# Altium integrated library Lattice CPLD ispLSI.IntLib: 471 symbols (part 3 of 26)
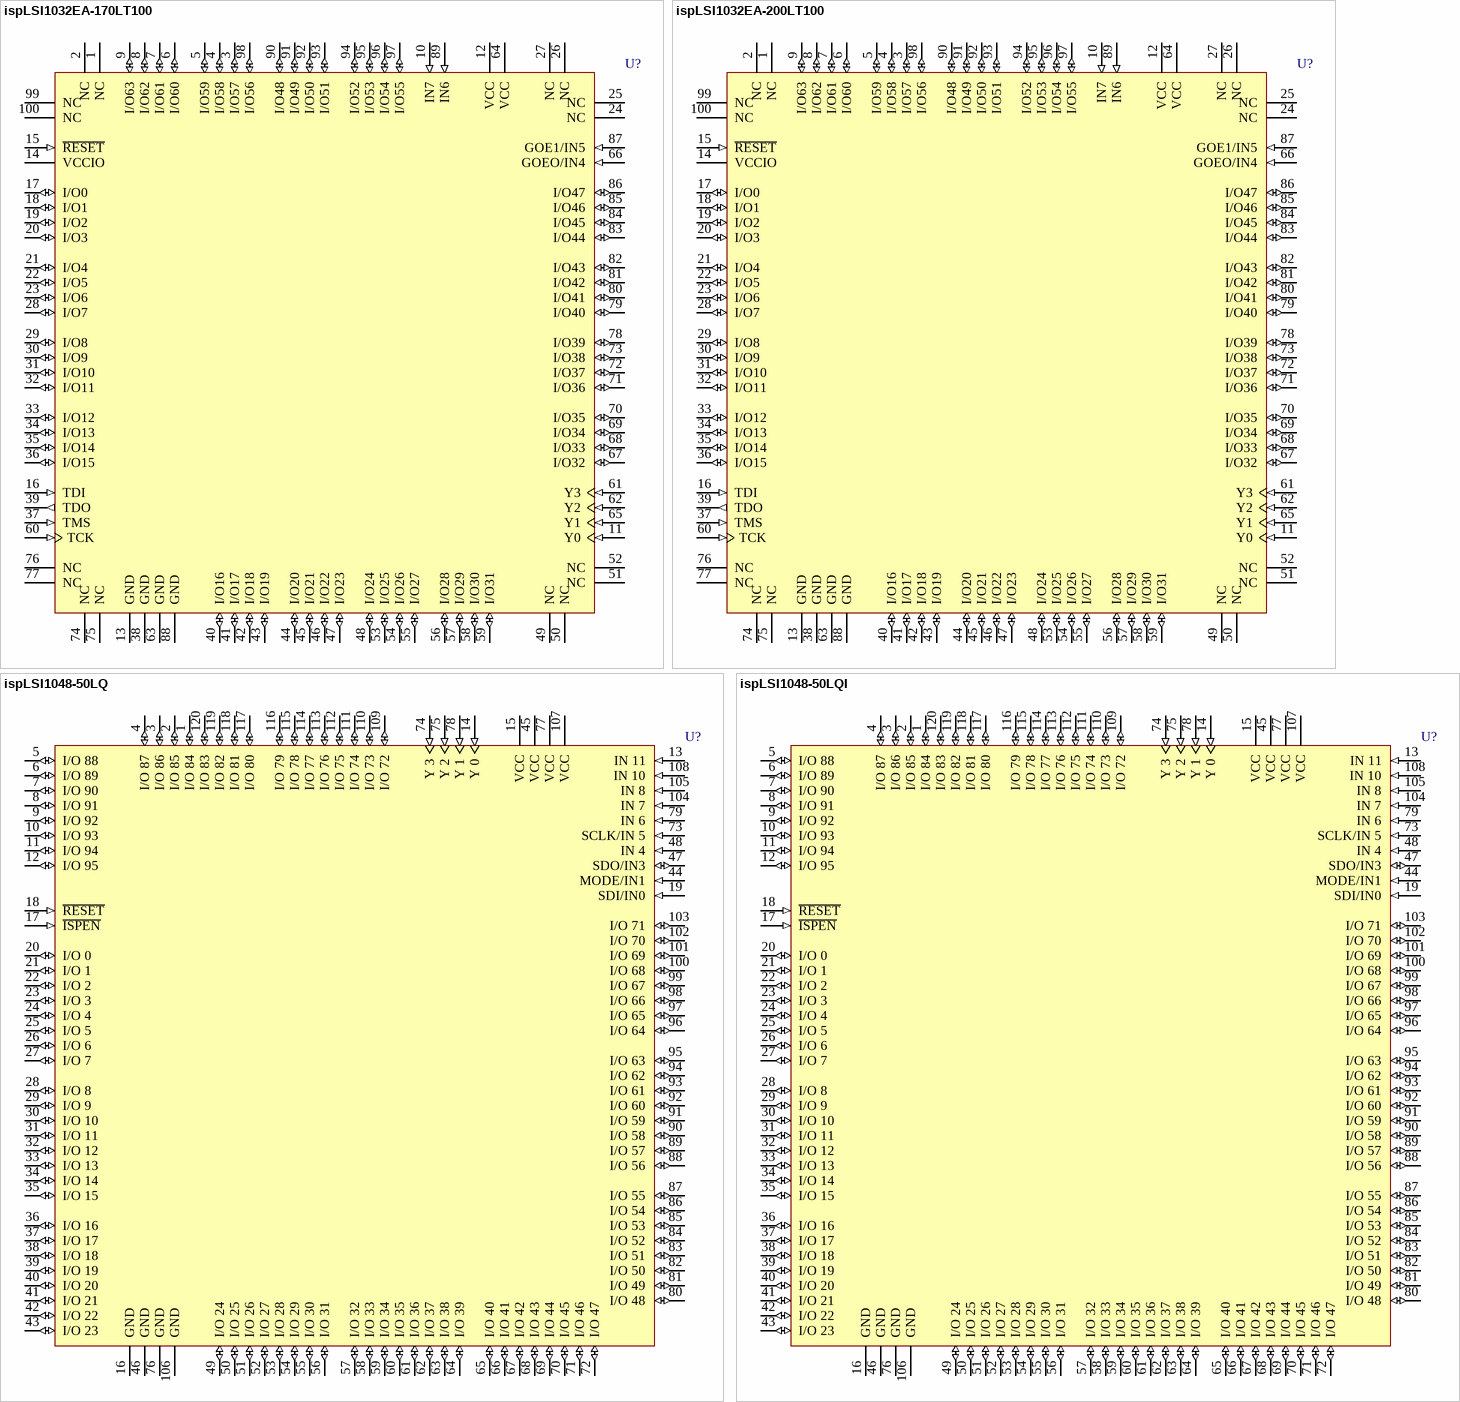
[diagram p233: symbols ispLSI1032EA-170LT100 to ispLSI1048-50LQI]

## ispLSI1032EA-200LT100
designator U?
In-System Programmable High-Density PLD; Note: Pins 66 and 87 have dual function capability which is software selectable.
footprint TQFP100_N (Thin QFP, 100-Leads, Body 14x14mm, Pitch 0.5mm, IPC Medium Density)
footprint TQFP100_L (Thin QFP, 100-Leads, Body 14x14mm, Pitch 0.5mm, IPC High Density)
footprint TQFP100_M (Thin QFP, 100-Leads, Body 14x14mm, Pitch 0.5mm, IPC Low Density)
3D model 1032EA-TQFP100 (100-Pin Thin Quad Flat Pack (TQFP100))
pins: 1 NC, 2 NC, 3 I/O57 (io), 4 I/O58 (io), 5 I/O59 (io), 6 I/O60 (io), 7 I/O61 (io), 8 I/O62 (io), 9 I/O63 (io), 10 IN7 (in), 11 Y0 (in), 12 VCC (power), 13 GND (power), 14 VCCIO (power), 15 ~{RESET} (in), 16 TDI (in), 17 I/O0 (io), 18 I/O1 (io), 19 I/O2 (io), 20 I/O3 (io), 21 I/O4 (io), 22 I/O5 (io), 23 I/O6 (io), 24 NC, 25 NC, 26 NC, 27 NC, 28 I/O7 (io), 29 I/O8 (io), 30 I/O9 (io), 31 I/O10 (io), 32 I/O11 (io), 33 I/O12 (io), 34 I/O13 (io), 35 I/O14 (io), 36 I/O15 (io), 37 TMS (in), 38 GND (power), 39 TDO (out), 40 I/O16 (io), 41 I/O17 (io), 42 I/O18 (io), 43 I/O19 (io), 44 I/O20 (io), 45 I/O21 (io), 46 I/O22 (io), 47 I/O23 (io), 48 I/O24 (io), 49 NC, 50 NC, 51 NC, 52 NC, 53 I/O25 (io), 54 I/O26 (io), 55 I/O27 (io), 56 I/O28 (io), 57 I/O29 (io), 58 I/O30 (io), 59 I/O31 (io), 60 TCK (in), 61 Y3 (in), 62 Y2 (in), 63 GND (power), 64 VCC (power), 65 Y1 (in), 66 GOEO/IN4 (in), 67 I/O32 (io), 68 I/O33 (io), 69 I/O34 (io), 70 I/O35 (io), 71 I/O36 (io), 72 I/O37 (io), 73 I/O38 (io), 74 NC, 75 NC, 76 NC, 77 NC, 78 I/O39 (io), 79 I/O40 (io), 80 I/O41 (io), 81 I/O42 (io), 82 I/O43 (io), 83 I/O44 (io), 84 I/O45 (io), 85 I/O46 (io), 86 I/O47 (io), 87 GOE1/IN5 (in), 88 GND (power), 89 IN6 (in), 90 I/O48 (io), 91 I/O49 (io), 92 I/O50 (io), 93 I/O51 (io), 94 I/O52 (io), 95 I/O53 (io), 96 I/O54 (io), 97 I/O55 (io), 98 I/O56 (io), 99 NC, 100 NC

## ispLSI1048-50LQ
designator U?
High-Density Programmable Logic
footprint PQFP120_N (QFP, 120-Leads, Body 28x28mm, Pitch 0.8mm, IPC Medium Density)
footprint PQFP120_L (QFP, 120-Leads, Body 28x28mm, Pitch 0.8mm, IPC High Density)
footprint PQFP120_M (QFP, 120-Leads, Body 28x28mm, Pitch 0.8mm, IPC Low Density)
3D model 1048-PQFP120 (120-Pin Quad Flat Pack 0.8 mm Pitch)
pins: 1 I/O 84 (io), 2 I/O 85 (io), 3 I/O 86 (io), 4 I/O 87 (io), 5 I/O 88 (io), 6 I/O 89 (io), 7 I/O 90 (io), 8 I/O 91 (io), 9 I/O 92 (io), 10 I/O 93 (io), 11 I/O 94 (io), 12 I/O 95 (io), 13 IN 11 (in), 14 Y 0 (in), 15 VCC (power), 16 GND (power), 17 ~{ISPEN} (in), 18 ~{RESET} (in), 19 SDI/IN0 (in), 20 I/O 0 (io), 21 I/O 1 (io), 22 I/O 2 (io), 23 I/O 3 (io), 24 I/O 4 (io), 25 I/O 5 (io), 26 I/O 6 (io), 27 I/O 7 (io), 28 I/O 8 (io), 29 I/O 9 (io), 30 I/O 10 (io), 31 I/O 11 (io), 32 I/O 12 (io), 33 I/O 13 (io), 34 I/O 14 (io), 35 I/O 15 (io), 36 I/O 16 (io), 37 I/O 17 (io), 38 I/O 18 (io), 39 I/O 19 (io), 40 I/O 20 (io), 41 I/O 21 (io), 42 I/O 22 (io), 43 I/O 23 (io), 44 MODE/IN1 (in), 45 VCC (power), 46 GND (power), 47 SDO/IN3 (io), 48 IN 4 (in), 49 I/O 24 (io), 50 I/O 25 (io), 51 I/O 26 (io), 52 I/O 27 (io), 53 I/O 28 (io), 54 I/O 29 (io), 55 I/O 30 (io), 56 I/O 31 (io), 57 I/O 32 (io), 58 I/O 33 (io), 59 I/O 34 (io), 60 I/O 35 (io), 61 I/O 36 (io), 62 I/O 37 (io), 63 I/O 38 (io), 64 I/O 39 (io), 65 I/O 40 (io), 66 I/O 41 (io), 67 I/O 42 (io), 68 I/O 43 (io), 69 I/O 44 (io), 70 I/O 45 (io), 71 I/O 46 (io), 72 I/O 47 (io), 73 SCLK/IN 5 (in), 74 Y 3 (in), 75 Y 2 (in), 76 GND (power), 77 VCC (power), 78 Y 1 (in), 79 IN 6 (in), 80 I/O 48 (io), 81 I/O 49 (io), 82 I/O 50 (io), 83 I/O 51 (io), 84 I/O 52 (io), 85 I/O 53 (io), 86 I/O 54 (io), 87 I/O 55 (io), 88 I/O 56 (io), 89 I/O 57 (io), 90 I/O 58 (io), 91 I/O 59 (io), 92 I/O 60 (io), 93 I/O 61 (io), 94 I/O 62 (io), 95 I/O 63 (io), 96 I/O 64 (io), 97 I/O 65 (io), 98 I/O 66 (io), 99 I/O 67 (io), 100 I/O 68 (io), 101 I/O 69 (io), 102 I/O 70 (io), 103 I/O 71 (io), 104 IN 7 (in), 105 IN 8 (in), 106 GND (power), 107 VCC (power), 108 IN 10 (in), 109 I/O 72 (io), 110 I/O 73 (io), 111 I/O 74 (io), 112 I/O 75 (io), 113 I/O 76 (io), 114 I/O 77 (io), 115 I/O 78 (io), 116 I/O 79 (io), 117 I/O 80 (io), 118 I/O 81 (io), 119 I/O 82 (io), 120 I/O 83 (io)

## ispLSI1048-50LQI
designator U?
High-Density Programmable Logic
footprint PQFP120_N (QFP, 120-Leads, Body 28x28mm, Pitch 0.8mm, IPC Medium Density)
footprint PQFP120_L (QFP, 120-Leads, Body 28x28mm, Pitch 0.8mm, IPC High Density)
footprint PQFP120_M (QFP, 120-Leads, Body 28x28mm, Pitch 0.8mm, IPC Low Density)
3D model 1048-PQFP120 (120-Pin Quad Flat Pack 0.8 mm Pitch)
pins: 1 I/O 84 (io), 2 I/O 85 (io), 3 I/O 86 (io), 4 I/O 87 (io), 5 I/O 88 (io), 6 I/O 89 (io), 7 I/O 90 (io), 8 I/O 91 (io), 9 I/O 92 (io), 10 I/O 93 (io), 11 I/O 94 (io), 12 I/O 95 (io), 13 IN 11 (in), 14 Y 0 (in), 15 VCC (power), 16 GND (power), 17 ~{ISPEN} (in), 18 ~{RESET} (in), 19 SDI/IN0 (in), 20 I/O 0 (io), 21 I/O 1 (io), 22 I/O 2 (io), 23 I/O 3 (io), 24 I/O 4 (io), 25 I/O 5 (io), 26 I/O 6 (io), 27 I/O 7 (io), 28 I/O 8 (io), 29 I/O 9 (io), 30 I/O 10 (io), 31 I/O 11 (io), 32 I/O 12 (io), 33 I/O 13 (io), 34 I/O 14 (io), 35 I/O 15 (io), 36 I/O 16 (io), 37 I/O 17 (io), 38 I/O 18 (io), 39 I/O 19 (io), 40 I/O 20 (io), 41 I/O 21 (io), 42 I/O 22 (io), 43 I/O 23 (io), 44 MODE/IN1 (in), 45 VCC (power), 46 GND (power), 47 SDO/IN3 (io), 48 IN 4 (in), 49 I/O 24 (io), 50 I/O 25 (io), 51 I/O 26 (io), 52 I/O 27 (io), 53 I/O 28 (io), 54 I/O 29 (io), 55 I/O 30 (io), 56 I/O 31 (io), 57 I/O 32 (io), 58 I/O 33 (io), 59 I/O 34 (io), 60 I/O 35 (io), 61 I/O 36 (io), 62 I/O 37 (io), 63 I/O 38 (io), 64 I/O 39 (io), 65 I/O 40 (io), 66 I/O 41 (io), 67 I/O 42 (io), 68 I/O 43 (io), 69 I/O 44 (io), 70 I/O 45 (io), 71 I/O 46 (io), 72 I/O 47 (io), 73 SCLK/IN 5 (in), 74 Y 3 (in), 75 Y 2 (in), 76 GND (power), 77 VCC (power), 78 Y 1 (in), 79 IN 6 (in), 80 I/O 48 (io), 81 I/O 49 (io), 82 I/O 50 (io), 83 I/O 51 (io), 84 I/O 52 (io), 85 I/O 53 (io), 86 I/O 54 (io), 87 I/O 55 (io), 88 I/O 56 (io), 89 I/O 57 (io), 90 I/O 58 (io), 91 I/O 59 (io), 92 I/O 60 (io), 93 I/O 61 (io), 94 I/O 62 (io), 95 I/O 63 (io), 96 I/O 64 (io), 97 I/O 65 (io), 98 I/O 66 (io), 99 I/O 67 (io), 100 I/O 68 (io), 101 I/O 69 (io), 102 I/O 70 (io), 103 I/O 71 (io), 104 IN 7 (in), 105 IN 8 (in), 106 GND (power), 107 VCC (power), 108 IN 10 (in), 109 I/O 72 (io), 110 I/O 73 (io), 111 I/O 74 (io), 112 I/O 75 (io), 113 I/O 76 (io), 114 I/O 77 (io), 115 I/O 78 (io), 116 I/O 79 (io), 117 I/O 80 (io), 118 I/O 81 (io), 119 I/O 82 (io), 120 I/O 83 (io)

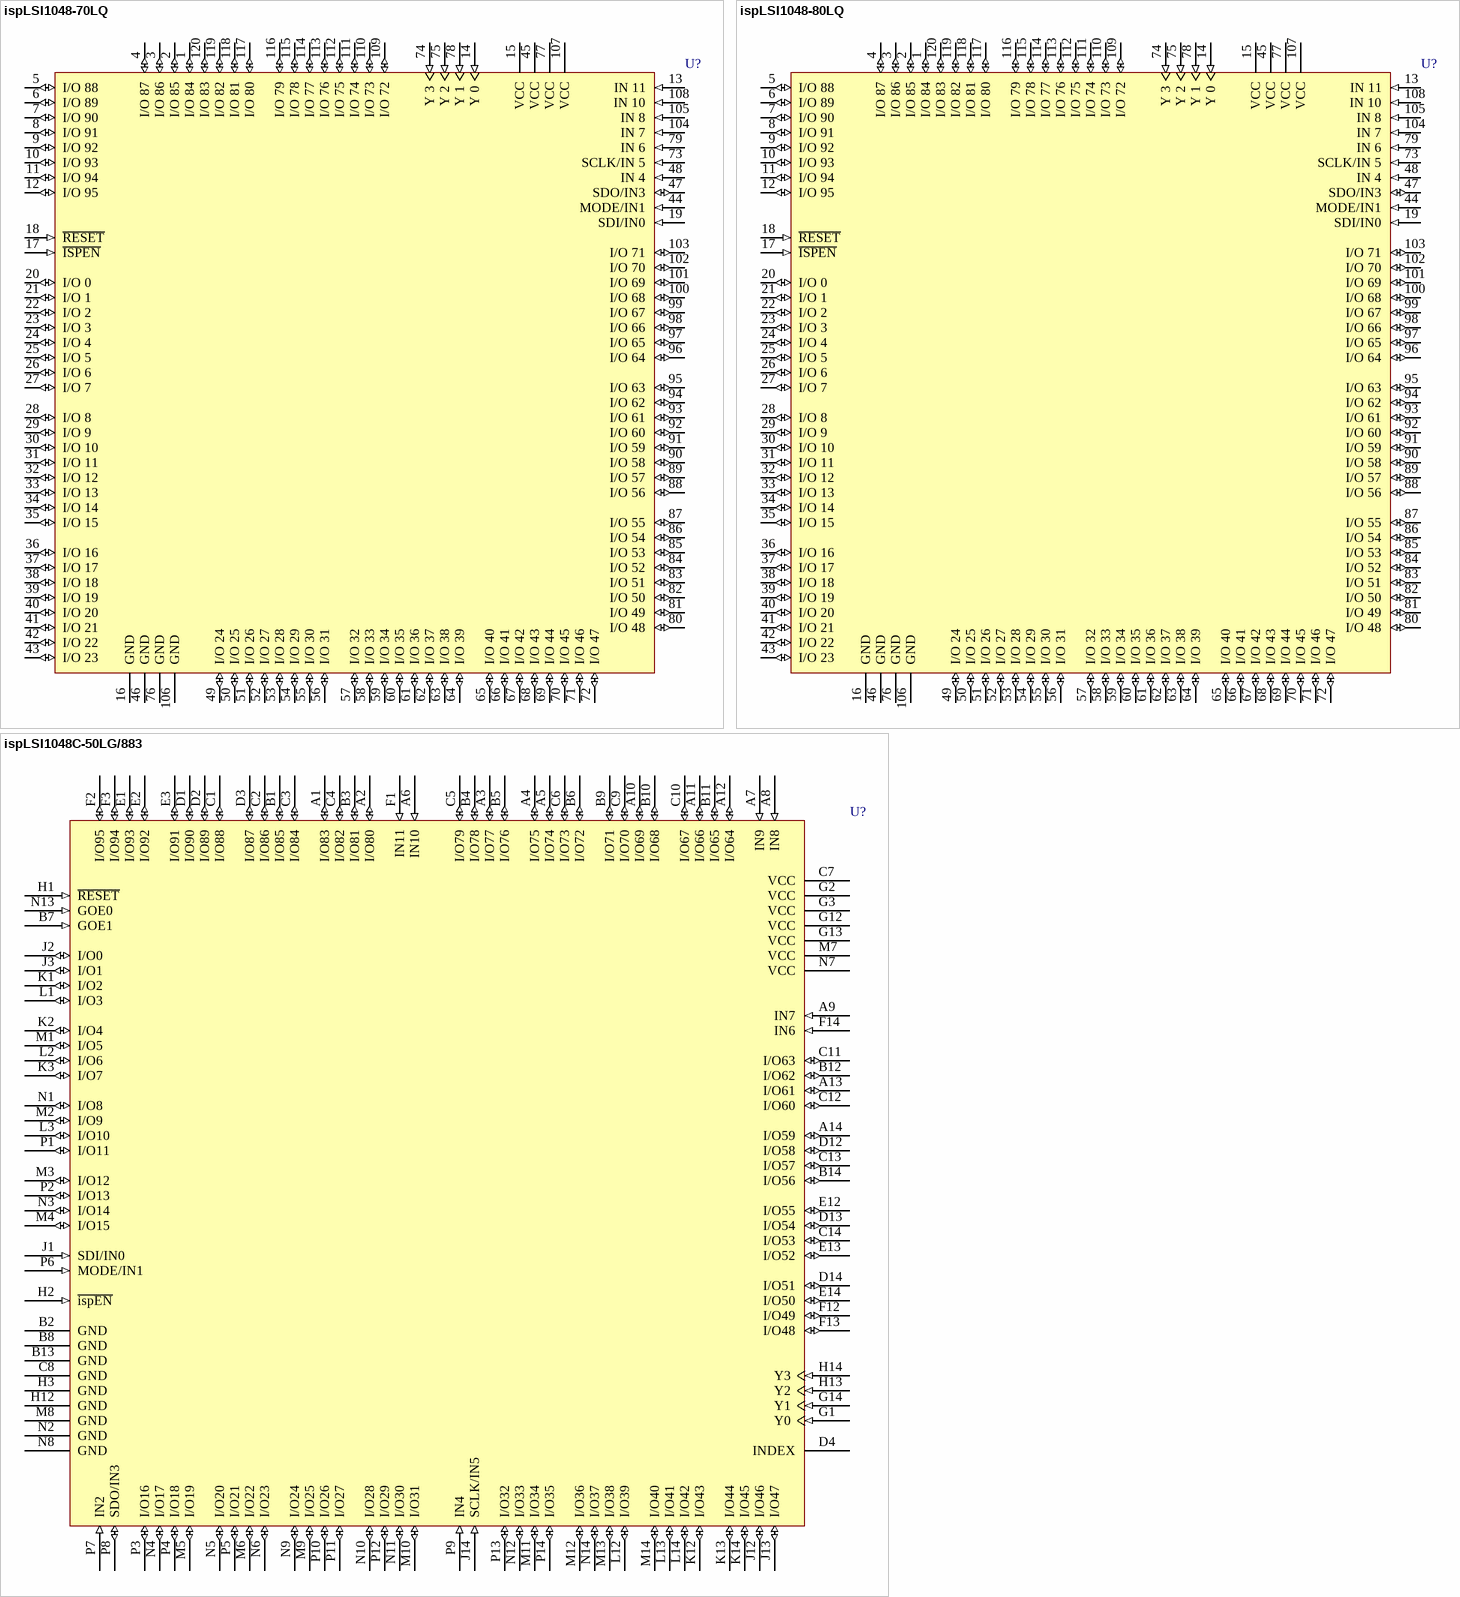
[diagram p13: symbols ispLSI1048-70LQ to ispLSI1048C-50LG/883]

## ispLSI1048-70LQ
designator U?
High-Density Programmable Logic
footprint PQFP120_N (QFP, 120-Leads, Body 28x28mm, Pitch 0.8mm, IPC Medium Density)
footprint PQFP120_L (QFP, 120-Leads, Body 28x28mm, Pitch 0.8mm, IPC High Density)
footprint PQFP120_M (QFP, 120-Leads, Body 28x28mm, Pitch 0.8mm, IPC Low Density)
3D model 1048-PQFP120 (120-Pin Quad Flat Pack 0.8 mm Pitch)
pins: 1 I/O 84 (io), 2 I/O 85 (io), 3 I/O 86 (io), 4 I/O 87 (io), 5 I/O 88 (io), 6 I/O 89 (io), 7 I/O 90 (io), 8 I/O 91 (io), 9 I/O 92 (io), 10 I/O 93 (io), 11 I/O 94 (io), 12 I/O 95 (io), 13 IN 11 (in), 14 Y 0 (in), 15 VCC (power), 16 GND (power), 17 ~{ISPEN} (in), 18 ~{RESET} (in), 19 SDI/IN0 (in), 20 I/O 0 (io), 21 I/O 1 (io), 22 I/O 2 (io), 23 I/O 3 (io), 24 I/O 4 (io), 25 I/O 5 (io), 26 I/O 6 (io), 27 I/O 7 (io), 28 I/O 8 (io), 29 I/O 9 (io), 30 I/O 10 (io), 31 I/O 11 (io), 32 I/O 12 (io), 33 I/O 13 (io), 34 I/O 14 (io), 35 I/O 15 (io), 36 I/O 16 (io), 37 I/O 17 (io), 38 I/O 18 (io), 39 I/O 19 (io), 40 I/O 20 (io), 41 I/O 21 (io), 42 I/O 22 (io), 43 I/O 23 (io), 44 MODE/IN1 (in), 45 VCC (power), 46 GND (power), 47 SDO/IN3 (io), 48 IN 4 (in), 49 I/O 24 (io), 50 I/O 25 (io), 51 I/O 26 (io), 52 I/O 27 (io), 53 I/O 28 (io), 54 I/O 29 (io), 55 I/O 30 (io), 56 I/O 31 (io), 57 I/O 32 (io), 58 I/O 33 (io), 59 I/O 34 (io), 60 I/O 35 (io), 61 I/O 36 (io), 62 I/O 37 (io), 63 I/O 38 (io), 64 I/O 39 (io), 65 I/O 40 (io), 66 I/O 41 (io), 67 I/O 42 (io), 68 I/O 43 (io), 69 I/O 44 (io), 70 I/O 45 (io), 71 I/O 46 (io), 72 I/O 47 (io), 73 SCLK/IN 5 (in), 74 Y 3 (in), 75 Y 2 (in), 76 GND (power), 77 VCC (power), 78 Y 1 (in), 79 IN 6 (in), 80 I/O 48 (io), 81 I/O 49 (io), 82 I/O 50 (io), 83 I/O 51 (io), 84 I/O 52 (io), 85 I/O 53 (io), 86 I/O 54 (io), 87 I/O 55 (io), 88 I/O 56 (io), 89 I/O 57 (io), 90 I/O 58 (io), 91 I/O 59 (io), 92 I/O 60 (io), 93 I/O 61 (io), 94 I/O 62 (io), 95 I/O 63 (io), 96 I/O 64 (io), 97 I/O 65 (io), 98 I/O 66 (io), 99 I/O 67 (io), 100 I/O 68 (io), 101 I/O 69 (io), 102 I/O 70 (io), 103 I/O 71 (io), 104 IN 7 (in), 105 IN 8 (in), 106 GND (power), 107 VCC (power), 108 IN 10 (in), 109 I/O 72 (io), 110 I/O 73 (io), 111 I/O 74 (io), 112 I/O 75 (io), 113 I/O 76 (io), 114 I/O 77 (io), 115 I/O 78 (io), 116 I/O 79 (io), 117 I/O 80 (io), 118 I/O 81 (io), 119 I/O 82 (io), 120 I/O 83 (io)

## ispLSI1048-80LQ
designator U?
High-Density Programmable Logic
footprint PQFP120_N (QFP, 120-Leads, Body 28x28mm, Pitch 0.8mm, IPC Medium Density)
footprint PQFP120_L (QFP, 120-Leads, Body 28x28mm, Pitch 0.8mm, IPC High Density)
footprint PQFP120_M (QFP, 120-Leads, Body 28x28mm, Pitch 0.8mm, IPC Low Density)
3D model 1048-PQFP120 (120-Pin Quad Flat Pack 0.8 mm Pitch)
pins: 1 I/O 84 (io), 2 I/O 85 (io), 3 I/O 86 (io), 4 I/O 87 (io), 5 I/O 88 (io), 6 I/O 89 (io), 7 I/O 90 (io), 8 I/O 91 (io), 9 I/O 92 (io), 10 I/O 93 (io), 11 I/O 94 (io), 12 I/O 95 (io), 13 IN 11 (in), 14 Y 0 (in), 15 VCC (power), 16 GND (power), 17 ~{ISPEN} (in), 18 ~{RESET} (in), 19 SDI/IN0 (in), 20 I/O 0 (io), 21 I/O 1 (io), 22 I/O 2 (io), 23 I/O 3 (io), 24 I/O 4 (io), 25 I/O 5 (io), 26 I/O 6 (io), 27 I/O 7 (io), 28 I/O 8 (io), 29 I/O 9 (io), 30 I/O 10 (io), 31 I/O 11 (io), 32 I/O 12 (io), 33 I/O 13 (io), 34 I/O 14 (io), 35 I/O 15 (io), 36 I/O 16 (io), 37 I/O 17 (io), 38 I/O 18 (io), 39 I/O 19 (io), 40 I/O 20 (io), 41 I/O 21 (io), 42 I/O 22 (io), 43 I/O 23 (io), 44 MODE/IN1 (in), 45 VCC (power), 46 GND (power), 47 SDO/IN3 (io), 48 IN 4 (in), 49 I/O 24 (io), 50 I/O 25 (io), 51 I/O 26 (io), 52 I/O 27 (io), 53 I/O 28 (io), 54 I/O 29 (io), 55 I/O 30 (io), 56 I/O 31 (io), 57 I/O 32 (io), 58 I/O 33 (io), 59 I/O 34 (io), 60 I/O 35 (io), 61 I/O 36 (io), 62 I/O 37 (io), 63 I/O 38 (io), 64 I/O 39 (io), 65 I/O 40 (io), 66 I/O 41 (io), 67 I/O 42 (io), 68 I/O 43 (io), 69 I/O 44 (io), 70 I/O 45 (io), 71 I/O 46 (io), 72 I/O 47 (io), 73 SCLK/IN 5 (in), 74 Y 3 (in), 75 Y 2 (in), 76 GND (power), 77 VCC (power), 78 Y 1 (in), 79 IN 6 (in), 80 I/O 48 (io), 81 I/O 49 (io), 82 I/O 50 (io), 83 I/O 51 (io), 84 I/O 52 (io), 85 I/O 53 (io), 86 I/O 54 (io), 87 I/O 55 (io), 88 I/O 56 (io), 89 I/O 57 (io), 90 I/O 58 (io), 91 I/O 59 (io), 92 I/O 60 (io), 93 I/O 61 (io), 94 I/O 62 (io), 95 I/O 63 (io), 96 I/O 64 (io), 97 I/O 65 (io), 98 I/O 66 (io), 99 I/O 67 (io), 100 I/O 68 (io), 101 I/O 69 (io), 102 I/O 70 (io), 103 I/O 71 (io), 104 IN 7 (in), 105 IN 8 (in), 106 GND (power), 107 VCC (power), 108 IN 10 (in), 109 I/O 72 (io), 110 I/O 73 (io), 111 I/O 74 (io), 112 I/O 75 (io), 113 I/O 76 (io), 114 I/O 77 (io), 115 I/O 78 (io), 116 I/O 79 (io), 117 I/O 80 (io), 118 I/O 81 (io), 119 I/O 82 (io), 120 I/O 83 (io)

## ispLSI1048C-50LG/883
designator U?
In-System Programmable High-Density PLD; Note: Pins J1, P6, P8 and J14 have dual function capability.
footprint CPGA133 (PGA, 133-Leads, Body 37x37mm, Pitch 2.54mm)
3D model 1048C-CPGA133 (133-Pin Pin Grid Array 2.54 mm Pitch)
pins: A1 I/O83 (io), A2 I/O80 (io), A3 I/O77 (io), A4 I/O75 (io), A5 I/O74 (io), A6 IN10 (in), A7 IN9 (in), A8 IN8 (in), A9 IN7 (in), A10 I/O69 (io), A11 I/O66 (io), A12 I/O64 (io), A13 I/O61 (io), A14 I/O59 (io), B1 I/O85 (io), B2 GND (power), B3 I/O81 (io), B4 I/O78 (io), B5 I/O76 (io), B6 I/O72 (io), B7 GOE1 (in), B8 GND (power), B9 I/O71 (io), B10 I/O68 (io), B11 I/O65 (io), B12 I/O62 (io), B13 GND (power), B14 I/O56 (io), C1 I/O88 (io), C2 I/O86 (io), C3 I/O84 (io), C4 I/O82 (io), C5 I/O79 (io), C6 I/O73 (io), C7 VCC (power), C8 GND (power), C9 I/O70 (io), C10 I/O67 (io), C11 I/O63 (io), C12 I/O60 (io), C13 I/O57 (io), C14 I/O53 (io), D1 I/O90 (io), D2 I/O89 (io), D3 I/O87 (io), D4 INDEX, D12 I/O58 (io), D13 I/O54 (io), D14 I/O51 (io), E1 I/O93 (io), E2 I/O92 (io), E3 I/O91 (io), E12 I/O55 (io), E13 I/O52 (io), E14 I/O50 (io), F1 IN11 (in), F2 I/O95 (io), F3 I/O94 (io), F12 I/O49 (io), F13 I/O48 (io), F14 IN6 (in), G1 Y0 (in), G2 VCC (power), G3 VCC (power), G12 VCC (power), G13 VCC (power), G14 Y1 (in), H1 ~{RESET} (in), H2 ~{ispEN} (in), H3 GND (power), H12 GND (power), H13 Y2 (in), H14 Y3 (in), J1 SDI/IN0 (in), J2 I/O0 (io), J3 I/O1 (io), J12 I/O46 (io), J13 I/O47 (io), J14 SCLK/IN5 (in), K1 I/O2 (io), K2 I/O4 (io), K3 I/O7 (io), K12 I/O43 (io), K13 I/O44 (io), K14 I/O45 (io), L1 I/O3 (io), L2 I/O6 (io), L3 I/O10 (io), L12 I/O39 (io), L13 I/O41 (io), L14 I/O42 (io), M1 I/O5 (io), M2 I/O9 (io), M3 I/O12 (io), M4 I/O15 (io), M5 I/O19 (io), M6 I/O22 (io), M7 VCC (power), M8 GND (power), M9 I/O25 (io), M10 I/O31 (io), M11 I/O34 (io), M12 I/O36 (io), M13 I/O38 (io), M14 I/O40 (io), N1 I/O8 (io), N2 GND (power), N3 I/O14 (io), N4 I/O17 (io), N5 I/O20 (io), N6 I/O23 (io), N7 VCC (power), N8 GND (power), N9 I/O24 (io), N10 I/O28 (io), N11 I/O30 (io), N12 I/O33 (io), N13 GOE0 (in), N14 I/O37 (io), P1 I/O11 (io), P2 I/O13 (io), P3 I/O16 (io), P4 I/O18 (io), P5 I/O21 (io), P6 MODE/IN1 (in), P7 IN2 (in), P8 SDO/IN3 (io), P9 IN4 (in), P10 I/O26 (io), P11 I/O27 (io), P12 I/O29 (io), P13 I/O32 (io), P14 I/O35 (io)

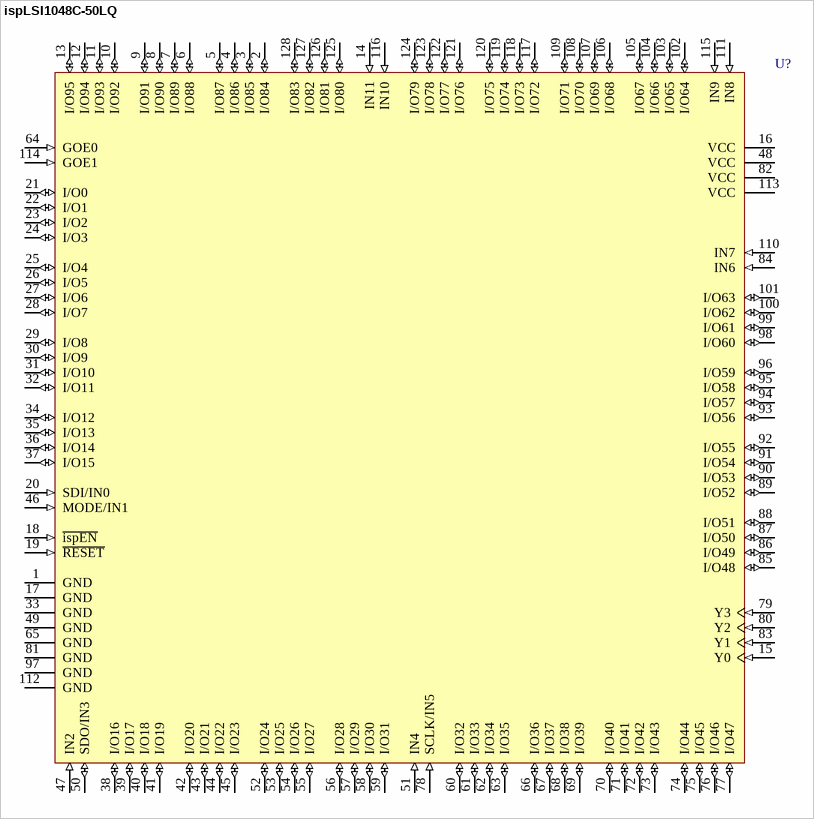
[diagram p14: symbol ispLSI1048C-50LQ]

## ispLSI1048C-50LQ
designator U?
In-System Programmable High-Density PLD; Note: Pins 20, 46, 50 and 78 have dual function capability.
footprint PQFP128_N (QFP, 128-Leads, Body 28x28mm, Pitch 0.8mm, IPC Medium Density)
footprint PQFP128_L (QFP, 128-Leads, Body 28x28mm, Pitch 0.8mm, IPC High Density)
footprint PQFP128_M (QFP, 128-Leads, Body 28x28mm, Pitch 0.8mm, IPC Low Density)
3D model 1048C-PQFP128 (128-Pin Quad Flat Pack 0.8 mm Pitch)
pins: 1 GND (power), 2 I/O84 (io), 3 I/O85 (io), 4 I/O86 (io), 5 I/O87 (io), 6 I/O88 (io), 7 I/O89 (io), 8 I/O90 (io), 9 I/O91 (io), 10 I/O92 (io), 11 I/O93 (io), 12 I/O94 (io), 13 I/O95 (io), 14 IN11 (in), 15 Y0 (in), 16 VCC (power), 17 GND (power), 18 ~{ispEN} (in), 19 ~{RESET} (in), 20 SDI/IN0 (in), 21 I/O0 (io), 22 I/O1 (io), 23 I/O2 (io), 24 I/O3 (io), 25 I/O4 (io), 26 I/O5 (io), 27 I/O6 (io), 28 I/O7 (io), 29 I/O8 (io), 30 I/O9 (io), 31 I/O10 (io), 32 I/O11 (io), 33 GND (power), 34 I/O12 (io), 35 I/O13 (io), 36 I/O14 (io), 37 I/O15 (io), 38 I/O16 (io), 39 I/O17 (io), 40 I/O18 (io), 41 I/O19 (io), 42 I/O20 (io), 43 I/O21 (io), 44 I/O22 (io), 45 I/O23 (io), 46 MODE/IN1 (in), 47 IN2 (in), 48 VCC (power), 49 GND (power), 50 SDO/IN3 (io), 51 IN4 (in), 52 I/O24 (io), 53 I/O25 (io), 54 I/O26 (io), 55 I/O27 (io), 56 I/O28 (io), 57 I/O29 (io), 58 I/O30 (io), 59 I/O31 (io), 60 I/O32 (io), 61 I/O33 (io), 62 I/O34 (io), 63 I/O35 (io), 64 GOE0 (in), 65 GND (power), 66 I/O36 (io), 67 I/O37 (io), 68 I/O38 (io), 69 I/O39 (io), 70 I/O40 (io), 71 I/O41 (io), 72 I/O42 (io), 73 I/O43 (io), 74 I/O44 (io), 75 I/O45 (io), 76 I/O46 (io), 77 I/O47 (io), 78 SCLK/IN5 (in), 79 Y3 (in), 80 Y2 (in), 81 GND (power), 82 VCC (power), 83 Y1 (in), 84 IN6 (in), 85 I/O48 (io), 86 I/O49 (io), 87 I/O50 (io), 88 I/O51 (io), 89 I/O52 (io), 90 I/O53 (io), 91 I/O54 (io), 92 I/O55 (io), 93 I/O56 (io), 94 I/O57 (io), 95 I/O58 (io), 96 I/O59 (io), 97 GND (power), 98 I/O60 (io), 99 I/O61 (io), 100 I/O62 (io), 101 I/O63 (io), 102 I/O64 (io), 103 I/O65 (io), 104 I/O66 (io), 105 I/O67 (io), 106 I/O68 (io), 107 I/O69 (io), 108 I/O70 (io), 109 I/O71 (io), 110 IN7 (in), 111 IN8 (in), 112 GND (power), 113 VCC (power), 114 GOE1 (in), 115 IN9 (in), 116 IN10 (in), 117 I/O72 (io), 118 I/O73 (io), 119 I/O74 (io), 120 I/O75 (io), 121 I/O76 (io), 122 I/O77 (io), 123 I/O78 (io), 124 I/O79 (io), 125 I/O80 (io), 126 I/O81 (io), 127 I/O82 (io), 128 I/O83 (io)

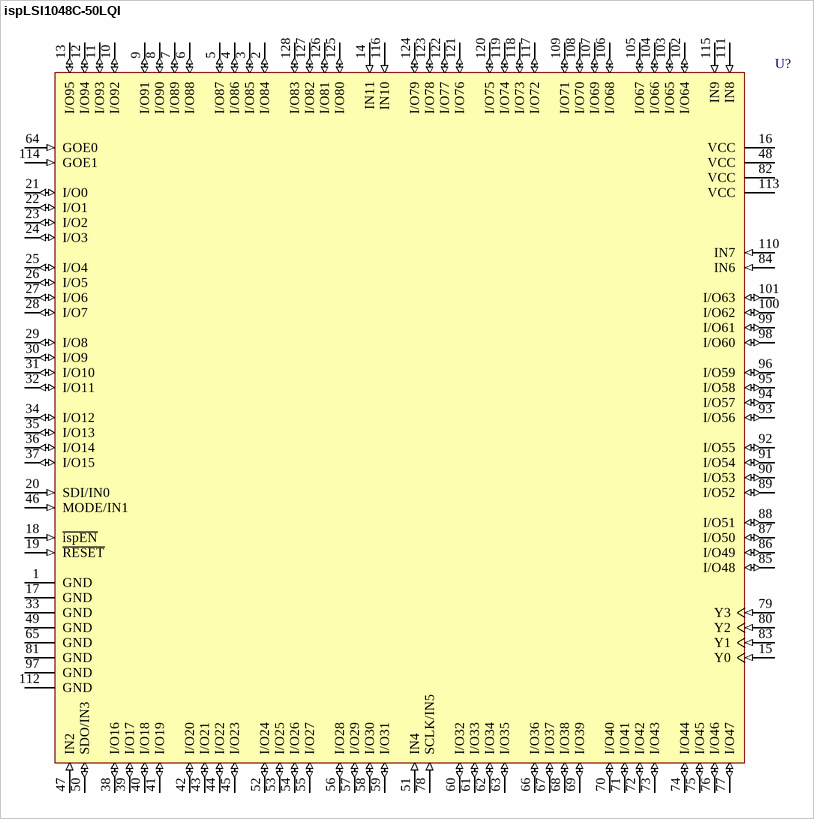
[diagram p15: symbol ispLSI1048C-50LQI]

## ispLSI1048C-50LQI
designator U?
In-System Programmable High-Density PLD; Note: Pins 20, 46, 50 and 78 have dual function capability.
footprint PQFP128_N (QFP, 128-Leads, Body 28x28mm, Pitch 0.8mm, IPC Medium Density)
footprint PQFP128_L (QFP, 128-Leads, Body 28x28mm, Pitch 0.8mm, IPC High Density)
footprint PQFP128_M (QFP, 128-Leads, Body 28x28mm, Pitch 0.8mm, IPC Low Density)
3D model 1048C-PQFP128 (128-Pin Quad Flat Pack 0.8 mm Pitch)
pins: 1 GND (power), 2 I/O84 (io), 3 I/O85 (io), 4 I/O86 (io), 5 I/O87 (io), 6 I/O88 (io), 7 I/O89 (io), 8 I/O90 (io), 9 I/O91 (io), 10 I/O92 (io), 11 I/O93 (io), 12 I/O94 (io), 13 I/O95 (io), 14 IN11 (in), 15 Y0 (in), 16 VCC (power), 17 GND (power), 18 ~{ispEN} (in), 19 ~{RESET} (in), 20 SDI/IN0 (in), 21 I/O0 (io), 22 I/O1 (io), 23 I/O2 (io), 24 I/O3 (io), 25 I/O4 (io), 26 I/O5 (io), 27 I/O6 (io), 28 I/O7 (io), 29 I/O8 (io), 30 I/O9 (io), 31 I/O10 (io), 32 I/O11 (io), 33 GND (power), 34 I/O12 (io), 35 I/O13 (io), 36 I/O14 (io), 37 I/O15 (io), 38 I/O16 (io), 39 I/O17 (io), 40 I/O18 (io), 41 I/O19 (io), 42 I/O20 (io), 43 I/O21 (io), 44 I/O22 (io), 45 I/O23 (io), 46 MODE/IN1 (in), 47 IN2 (in), 48 VCC (power), 49 GND (power), 50 SDO/IN3 (io), 51 IN4 (in), 52 I/O24 (io), 53 I/O25 (io), 54 I/O26 (io), 55 I/O27 (io), 56 I/O28 (io), 57 I/O29 (io), 58 I/O30 (io), 59 I/O31 (io), 60 I/O32 (io), 61 I/O33 (io), 62 I/O34 (io), 63 I/O35 (io), 64 GOE0 (in), 65 GND (power), 66 I/O36 (io), 67 I/O37 (io), 68 I/O38 (io), 69 I/O39 (io), 70 I/O40 (io), 71 I/O41 (io), 72 I/O42 (io), 73 I/O43 (io), 74 I/O44 (io), 75 I/O45 (io), 76 I/O46 (io), 77 I/O47 (io), 78 SCLK/IN5 (in), 79 Y3 (in), 80 Y2 (in), 81 GND (power), 82 VCC (power), 83 Y1 (in), 84 IN6 (in), 85 I/O48 (io), 86 I/O49 (io), 87 I/O50 (io), 88 I/O51 (io), 89 I/O52 (io), 90 I/O53 (io), 91 I/O54 (io), 92 I/O55 (io), 93 I/O56 (io), 94 I/O57 (io), 95 I/O58 (io), 96 I/O59 (io), 97 GND (power), 98 I/O60 (io), 99 I/O61 (io), 100 I/O62 (io), 101 I/O63 (io), 102 I/O64 (io), 103 I/O65 (io), 104 I/O66 (io), 105 I/O67 (io), 106 I/O68 (io), 107 I/O69 (io), 108 I/O70 (io), 109 I/O71 (io), 110 IN7 (in), 111 IN8 (in), 112 GND (power), 113 VCC (power), 114 GOE1 (in), 115 IN9 (in), 116 IN10 (in), 117 I/O72 (io), 118 I/O73 (io), 119 I/O74 (io), 120 I/O75 (io), 121 I/O76 (io), 122 I/O77 (io), 123 I/O78 (io), 124 I/O79 (io), 125 I/O80 (io), 126 I/O81 (io), 127 I/O82 (io), 128 I/O83 (io)

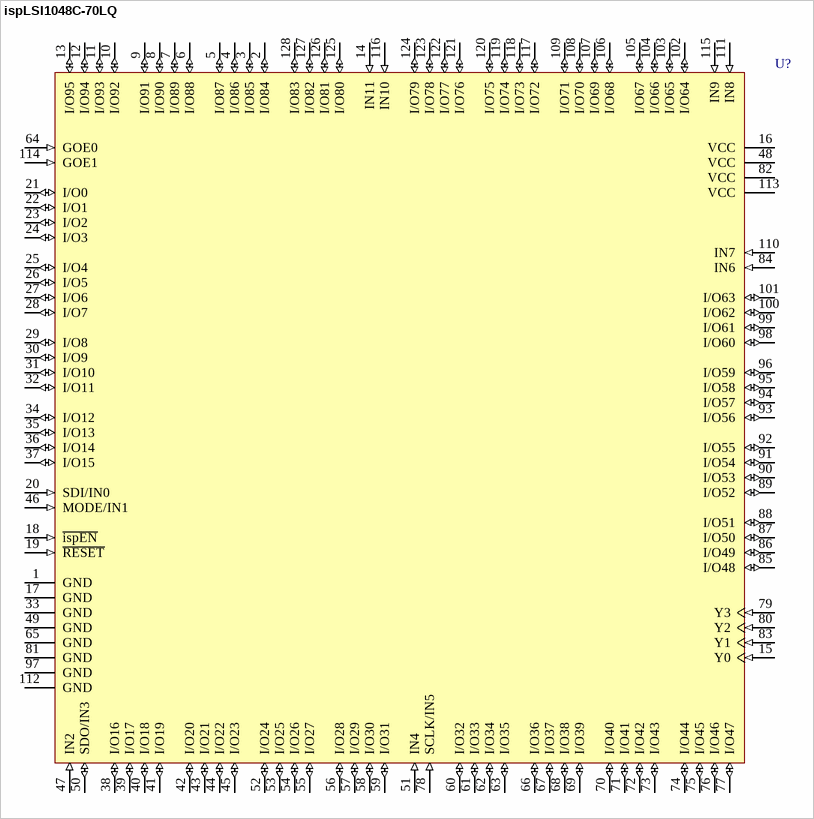
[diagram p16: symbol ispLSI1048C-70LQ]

## ispLSI1048C-70LQ
designator U?
In-System Programmable High-Density PLD; Note: Pins 20, 46, 50 and 78 have dual function capability.
footprint PQFP128_N (QFP, 128-Leads, Body 28x28mm, Pitch 0.8mm, IPC Medium Density)
footprint PQFP128_L (QFP, 128-Leads, Body 28x28mm, Pitch 0.8mm, IPC High Density)
footprint PQFP128_M (QFP, 128-Leads, Body 28x28mm, Pitch 0.8mm, IPC Low Density)
3D model 1048C-PQFP128 (128-Pin Quad Flat Pack 0.8 mm Pitch)
pins: 1 GND (power), 2 I/O84 (io), 3 I/O85 (io), 4 I/O86 (io), 5 I/O87 (io), 6 I/O88 (io), 7 I/O89 (io), 8 I/O90 (io), 9 I/O91 (io), 10 I/O92 (io), 11 I/O93 (io), 12 I/O94 (io), 13 I/O95 (io), 14 IN11 (in), 15 Y0 (in), 16 VCC (power), 17 GND (power), 18 ~{ispEN} (in), 19 ~{RESET} (in), 20 SDI/IN0 (in), 21 I/O0 (io), 22 I/O1 (io), 23 I/O2 (io), 24 I/O3 (io), 25 I/O4 (io), 26 I/O5 (io), 27 I/O6 (io), 28 I/O7 (io), 29 I/O8 (io), 30 I/O9 (io), 31 I/O10 (io), 32 I/O11 (io), 33 GND (power), 34 I/O12 (io), 35 I/O13 (io), 36 I/O14 (io), 37 I/O15 (io), 38 I/O16 (io), 39 I/O17 (io), 40 I/O18 (io), 41 I/O19 (io), 42 I/O20 (io), 43 I/O21 (io), 44 I/O22 (io), 45 I/O23 (io), 46 MODE/IN1 (in), 47 IN2 (in), 48 VCC (power), 49 GND (power), 50 SDO/IN3 (io), 51 IN4 (in), 52 I/O24 (io), 53 I/O25 (io), 54 I/O26 (io), 55 I/O27 (io), 56 I/O28 (io), 57 I/O29 (io), 58 I/O30 (io), 59 I/O31 (io), 60 I/O32 (io), 61 I/O33 (io), 62 I/O34 (io), 63 I/O35 (io), 64 GOE0 (in), 65 GND (power), 66 I/O36 (io), 67 I/O37 (io), 68 I/O38 (io), 69 I/O39 (io), 70 I/O40 (io), 71 I/O41 (io), 72 I/O42 (io), 73 I/O43 (io), 74 I/O44 (io), 75 I/O45 (io), 76 I/O46 (io), 77 I/O47 (io), 78 SCLK/IN5 (in), 79 Y3 (in), 80 Y2 (in), 81 GND (power), 82 VCC (power), 83 Y1 (in), 84 IN6 (in), 85 I/O48 (io), 86 I/O49 (io), 87 I/O50 (io), 88 I/O51 (io), 89 I/O52 (io), 90 I/O53 (io), 91 I/O54 (io), 92 I/O55 (io), 93 I/O56 (io), 94 I/O57 (io), 95 I/O58 (io), 96 I/O59 (io), 97 GND (power), 98 I/O60 (io), 99 I/O61 (io), 100 I/O62 (io), 101 I/O63 (io), 102 I/O64 (io), 103 I/O65 (io), 104 I/O66 (io), 105 I/O67 (io), 106 I/O68 (io), 107 I/O69 (io), 108 I/O70 (io), 109 I/O71 (io), 110 IN7 (in), 111 IN8 (in), 112 GND (power), 113 VCC (power), 114 GOE1 (in), 115 IN9 (in), 116 IN10 (in), 117 I/O72 (io), 118 I/O73 (io), 119 I/O74 (io), 120 I/O75 (io), 121 I/O76 (io), 122 I/O77 (io), 123 I/O78 (io), 124 I/O79 (io), 125 I/O80 (io), 126 I/O81 (io), 127 I/O82 (io), 128 I/O83 (io)

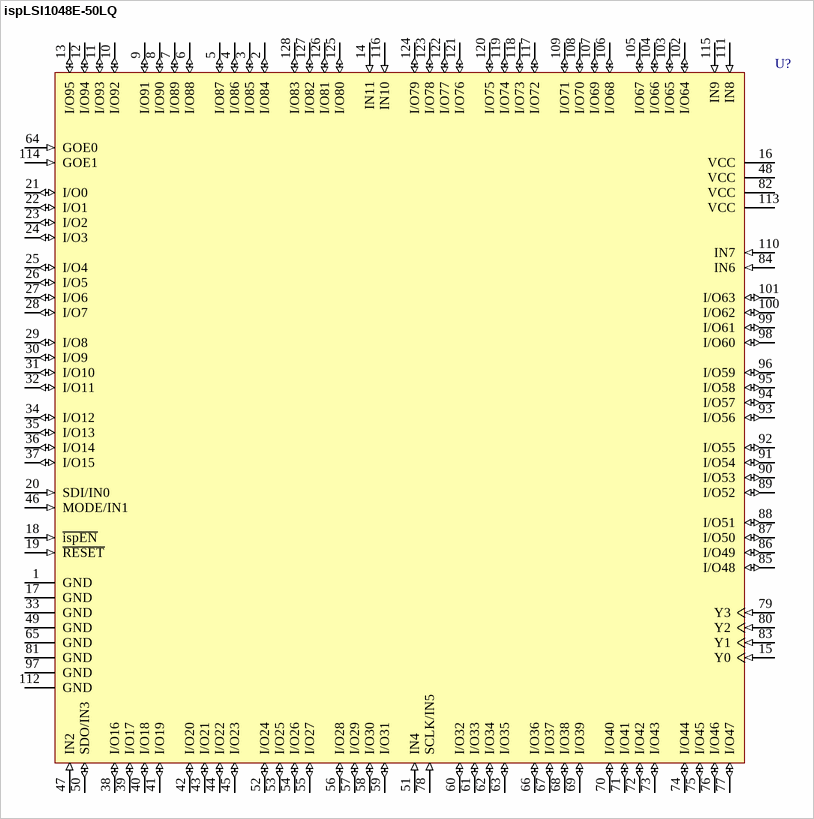
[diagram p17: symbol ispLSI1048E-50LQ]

## ispLSI1048E-50LQ
designator U?
In-System Programmable High-Density PLD; Note: Pins 20, 46, 50 and 78 have dual function capability.
footprint PQFP128_N (QFP, 128-Leads, Body 28x28mm, Pitch 0.8mm, IPC Medium Density)
footprint PQFP128_L (QFP, 128-Leads, Body 28x28mm, Pitch 0.8mm, IPC High Density)
footprint PQFP128_M (QFP, 128-Leads, Body 28x28mm, Pitch 0.8mm, IPC Low Density)
3D model 1048E-PQFP128 (128-Pin Quad Flat Pack 0.8 mm Pitch)
pins: 1 GND (power), 2 I/O84 (io), 3 I/O85 (io), 4 I/O86 (io), 5 I/O87 (io), 6 I/O88 (io), 7 I/O89 (io), 8 I/O90 (io), 9 I/O91 (io), 10 I/O92 (io), 11 I/O93 (io), 12 I/O94 (io), 13 I/O95 (io), 14 IN11 (in), 15 Y0 (in), 16 VCC (power), 17 GND (power), 18 ~{ispEN} (in), 19 ~{RESET} (in), 20 SDI/IN0 (in), 21 I/O0 (io), 22 I/O1 (io), 23 I/O2 (io), 24 I/O3 (io), 25 I/O4 (io), 26 I/O5 (io), 27 I/O6 (io), 28 I/O7 (io), 29 I/O8 (io), 30 I/O9 (io), 31 I/O10 (io), 32 I/O11 (io), 33 GND (power), 34 I/O12 (io), 35 I/O13 (io), 36 I/O14 (io), 37 I/O15 (io), 38 I/O16 (io), 39 I/O17 (io), 40 I/O18 (io), 41 I/O19 (io), 42 I/O20 (io), 43 I/O21 (io), 44 I/O22 (io), 45 I/O23 (io), 46 MODE/IN1 (in), 47 IN2 (in), 48 VCC (power), 49 GND (power), 50 SDO/IN3 (io), 51 IN4 (in), 52 I/O24 (io), 53 I/O25 (io), 54 I/O26 (io), 55 I/O27 (io), 56 I/O28 (io), 57 I/O29 (io), 58 I/O30 (io), 59 I/O31 (io), 60 I/O32 (io), 61 I/O33 (io), 62 I/O34 (io), 63 I/O35 (io), 64 GOE0 (in), 65 GND (power), 66 I/O36 (io), 67 I/O37 (io), 68 I/O38 (io), 69 I/O39 (io), 70 I/O40 (io), 71 I/O41 (io), 72 I/O42 (io), 73 I/O43 (io), 74 I/O44 (io), 75 I/O45 (io), 76 I/O46 (io), 77 I/O47 (io), 78 SCLK/IN5 (in), 79 Y3 (in), 80 Y2 (in), 81 GND (power), 82 VCC (power), 83 Y1 (in), 84 IN6 (in), 85 I/O48 (io), 86 I/O49 (io), 87 I/O50 (io), 88 I/O51 (io), 89 I/O52 (io), 90 I/O53 (io), 91 I/O54 (io), 92 I/O55 (io), 93 I/O56 (io), 94 I/O57 (io), 95 I/O58 (io), 96 I/O59 (io), 97 GND (power), 98 I/O60 (io), 99 I/O61 (io), 100 I/O62 (io), 101 I/O63 (io), 102 I/O64 (io), 103 I/O65 (io), 104 I/O66 (io), 105 I/O67 (io), 106 I/O68 (io), 107 I/O69 (io), 108 I/O70 (io), 109 I/O71 (io), 110 IN7 (in), 111 IN8 (in), 112 GND (power), 113 VCC (power), 114 GOE1 (in), 115 IN9 (in), 116 IN10 (in), 117 I/O72 (io), 118 I/O73 (io), 119 I/O74 (io), 120 I/O75 (io), 121 I/O76 (io), 122 I/O77 (io), 123 I/O78 (io), 124 I/O79 (io), 125 I/O80 (io), 126 I/O81 (io), 127 I/O82 (io), 128 I/O83 (io)

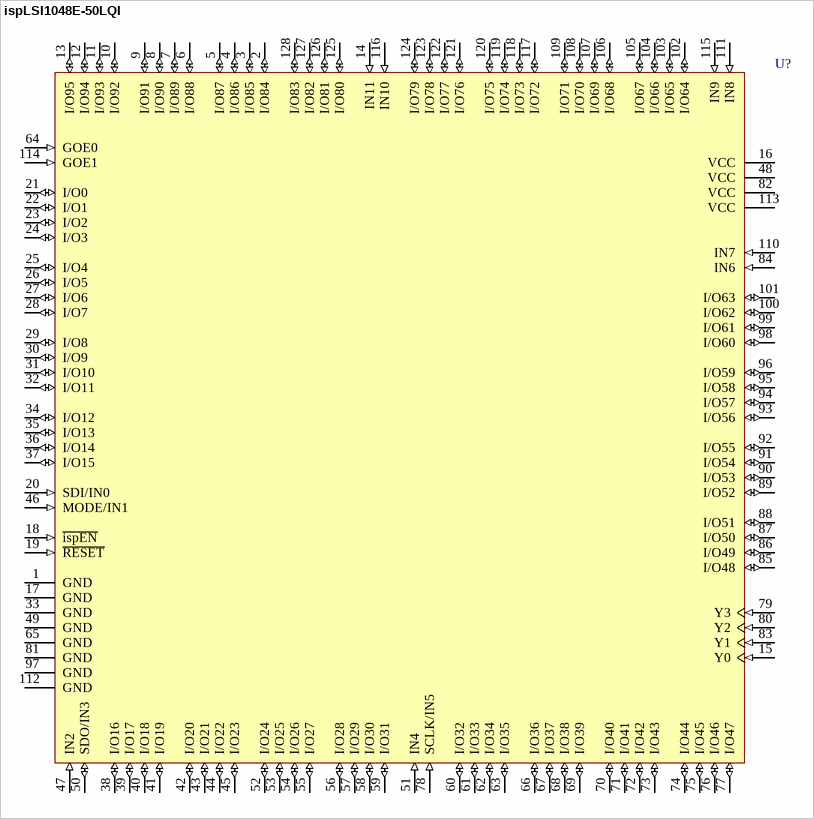
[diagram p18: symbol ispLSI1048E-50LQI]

## ispLSI1048E-50LQI
designator U?
In-System Programmable High-Density PLD; Note: Pins 20, 46, 50 and 78 have dual function capability.
footprint PQFP128_N (QFP, 128-Leads, Body 28x28mm, Pitch 0.8mm, IPC Medium Density)
footprint PQFP128_L (QFP, 128-Leads, Body 28x28mm, Pitch 0.8mm, IPC High Density)
footprint PQFP128_M (QFP, 128-Leads, Body 28x28mm, Pitch 0.8mm, IPC Low Density)
3D model 1048E-PQFP128 (128-Pin Quad Flat Pack 0.8 mm Pitch)
pins: 1 GND (power), 2 I/O84 (io), 3 I/O85 (io), 4 I/O86 (io), 5 I/O87 (io), 6 I/O88 (io), 7 I/O89 (io), 8 I/O90 (io), 9 I/O91 (io), 10 I/O92 (io), 11 I/O93 (io), 12 I/O94 (io), 13 I/O95 (io), 14 IN11 (in), 15 Y0 (in), 16 VCC (power), 17 GND (power), 18 ~{ispEN} (in), 19 ~{RESET} (in), 20 SDI/IN0 (in), 21 I/O0 (io), 22 I/O1 (io), 23 I/O2 (io), 24 I/O3 (io), 25 I/O4 (io), 26 I/O5 (io), 27 I/O6 (io), 28 I/O7 (io), 29 I/O8 (io), 30 I/O9 (io), 31 I/O10 (io), 32 I/O11 (io), 33 GND (power), 34 I/O12 (io), 35 I/O13 (io), 36 I/O14 (io), 37 I/O15 (io), 38 I/O16 (io), 39 I/O17 (io), 40 I/O18 (io), 41 I/O19 (io), 42 I/O20 (io), 43 I/O21 (io), 44 I/O22 (io), 45 I/O23 (io), 46 MODE/IN1 (in), 47 IN2 (in), 48 VCC (power), 49 GND (power), 50 SDO/IN3 (io), 51 IN4 (in), 52 I/O24 (io), 53 I/O25 (io), 54 I/O26 (io), 55 I/O27 (io), 56 I/O28 (io), 57 I/O29 (io), 58 I/O30 (io), 59 I/O31 (io), 60 I/O32 (io), 61 I/O33 (io), 62 I/O34 (io), 63 I/O35 (io), 64 GOE0 (in), 65 GND (power), 66 I/O36 (io), 67 I/O37 (io), 68 I/O38 (io), 69 I/O39 (io), 70 I/O40 (io), 71 I/O41 (io), 72 I/O42 (io), 73 I/O43 (io), 74 I/O44 (io), 75 I/O45 (io), 76 I/O46 (io), 77 I/O47 (io), 78 SCLK/IN5 (in), 79 Y3 (in), 80 Y2 (in), 81 GND (power), 82 VCC (power), 83 Y1 (in), 84 IN6 (in), 85 I/O48 (io), 86 I/O49 (io), 87 I/O50 (io), 88 I/O51 (io), 89 I/O52 (io), 90 I/O53 (io), 91 I/O54 (io), 92 I/O55 (io), 93 I/O56 (io), 94 I/O57 (io), 95 I/O58 (io), 96 I/O59 (io), 97 GND (power), 98 I/O60 (io), 99 I/O61 (io), 100 I/O62 (io), 101 I/O63 (io), 102 I/O64 (io), 103 I/O65 (io), 104 I/O66 (io), 105 I/O67 (io), 106 I/O68 (io), 107 I/O69 (io), 108 I/O70 (io), 109 I/O71 (io), 110 IN7 (in), 111 IN8 (in), 112 GND (power), 113 VCC (power), 114 GOE1 (in), 115 IN9 (in), 116 IN10 (in), 117 I/O72 (io), 118 I/O73 (io), 119 I/O74 (io), 120 I/O75 (io), 121 I/O76 (io), 122 I/O77 (io), 123 I/O78 (io), 124 I/O79 (io), 125 I/O80 (io), 126 I/O81 (io), 127 I/O82 (io), 128 I/O83 (io)

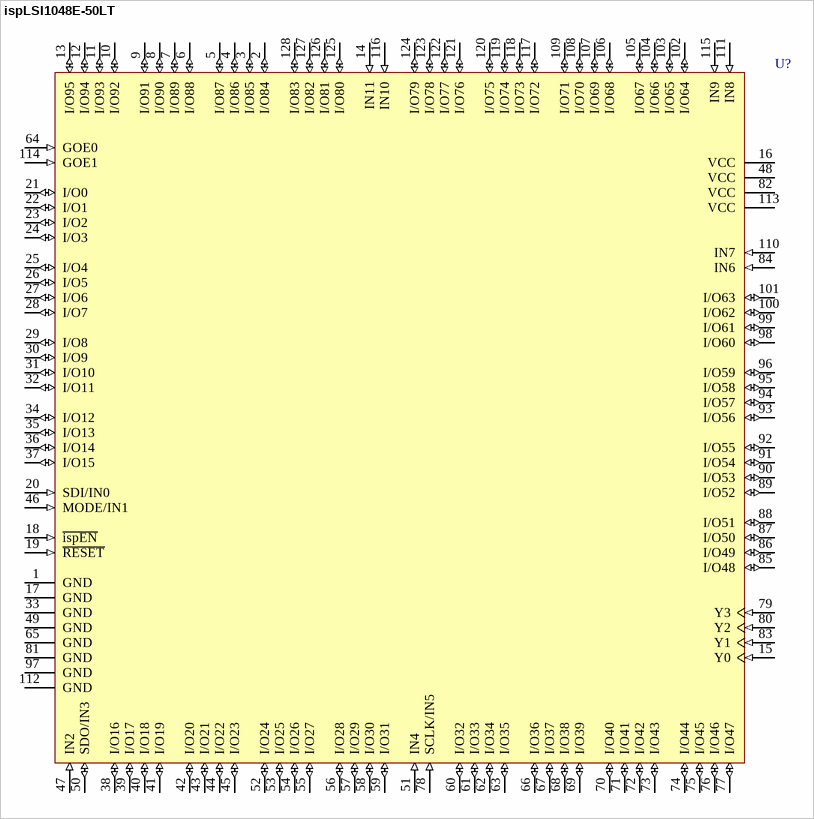
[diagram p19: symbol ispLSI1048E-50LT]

## ispLSI1048E-50LT
designator U?
In-System Programmable High-Density PLD; Note: Pins 20, 46, 50 and 78 have dual function capability.
footprint TQFP128_N (Thin QFP, 128-Leads, Body 14x14mm, Pitch 0.4mm, IPC Medium Density)
footprint TQFP128_L (Thin QFP, 128-Leads, Body 14x14mm, Pitch 0.4mm, IPC High Density)
footprint TQFP128_M (Thin QFP, 128-Leads, Body 14x14mm, Pitch 0.4mm, IPC Low Density)
3D model 1048E-TQFP128 (128-Pin Thin Quad Flat Pack 0.4 mm Pitch)
pins: 1 GND (power), 2 I/O84 (io), 3 I/O85 (io), 4 I/O86 (io), 5 I/O87 (io), 6 I/O88 (io), 7 I/O89 (io), 8 I/O90 (io), 9 I/O91 (io), 10 I/O92 (io), 11 I/O93 (io), 12 I/O94 (io), 13 I/O95 (io), 14 IN11 (in), 15 Y0 (in), 16 VCC (power), 17 GND (power), 18 ~{ispEN} (in), 19 ~{RESET} (in), 20 SDI/IN0 (in), 21 I/O0 (io), 22 I/O1 (io), 23 I/O2 (io), 24 I/O3 (io), 25 I/O4 (io), 26 I/O5 (io), 27 I/O6 (io), 28 I/O7 (io), 29 I/O8 (io), 30 I/O9 (io), 31 I/O10 (io), 32 I/O11 (io), 33 GND (power), 34 I/O12 (io), 35 I/O13 (io), 36 I/O14 (io), 37 I/O15 (io), 38 I/O16 (io), 39 I/O17 (io), 40 I/O18 (io), 41 I/O19 (io), 42 I/O20 (io), 43 I/O21 (io), 44 I/O22 (io), 45 I/O23 (io), 46 MODE/IN1 (in), 47 IN2 (in), 48 VCC (power), 49 GND (power), 50 SDO/IN3 (io), 51 IN4 (in), 52 I/O24 (io), 53 I/O25 (io), 54 I/O26 (io), 55 I/O27 (io), 56 I/O28 (io), 57 I/O29 (io), 58 I/O30 (io), 59 I/O31 (io), 60 I/O32 (io), 61 I/O33 (io), 62 I/O34 (io), 63 I/O35 (io), 64 GOE0 (in), 65 GND (power), 66 I/O36 (io), 67 I/O37 (io), 68 I/O38 (io), 69 I/O39 (io), 70 I/O40 (io), 71 I/O41 (io), 72 I/O42 (io), 73 I/O43 (io), 74 I/O44 (io), 75 I/O45 (io), 76 I/O46 (io), 77 I/O47 (io), 78 SCLK/IN5 (in), 79 Y3 (in), 80 Y2 (in), 81 GND (power), 82 VCC (power), 83 Y1 (in), 84 IN6 (in), 85 I/O48 (io), 86 I/O49 (io), 87 I/O50 (io), 88 I/O51 (io), 89 I/O52 (io), 90 I/O53 (io), 91 I/O54 (io), 92 I/O55 (io), 93 I/O56 (io), 94 I/O57 (io), 95 I/O58 (io), 96 I/O59 (io), 97 GND (power), 98 I/O60 (io), 99 I/O61 (io), 100 I/O62 (io), 101 I/O63 (io), 102 I/O64 (io), 103 I/O65 (io), 104 I/O66 (io), 105 I/O67 (io), 106 I/O68 (io), 107 I/O69 (io), 108 I/O70 (io), 109 I/O71 (io), 110 IN7 (in), 111 IN8 (in), 112 GND (power), 113 VCC (power), 114 GOE1 (in), 115 IN9 (in), 116 IN10 (in), 117 I/O72 (io), 118 I/O73 (io), 119 I/O74 (io), 120 I/O75 (io), 121 I/O76 (io), 122 I/O77 (io), 123 I/O78 (io), 124 I/O79 (io), 125 I/O80 (io), 126 I/O81 (io), 127 I/O82 (io), 128 I/O83 (io)

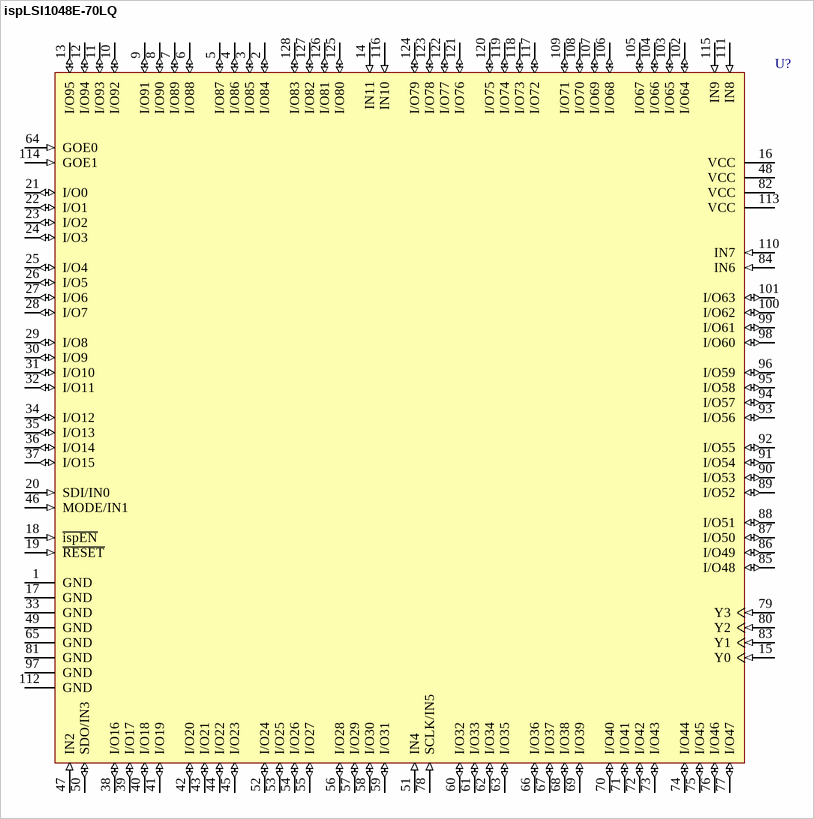
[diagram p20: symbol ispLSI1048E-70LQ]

## ispLSI1048E-70LQ
designator U?
In-System Programmable High-Density PLD; Note: Pins 20, 46, 50 and 78 have dual function capability.
footprint PQFP128_N (QFP, 128-Leads, Body 28x28mm, Pitch 0.8mm, IPC Medium Density)
footprint PQFP128_L (QFP, 128-Leads, Body 28x28mm, Pitch 0.8mm, IPC High Density)
footprint PQFP128_M (QFP, 128-Leads, Body 28x28mm, Pitch 0.8mm, IPC Low Density)
3D model 1048E-PQFP128 (128-Pin Quad Flat Pack 0.8 mm Pitch)
pins: 1 GND (power), 2 I/O84 (io), 3 I/O85 (io), 4 I/O86 (io), 5 I/O87 (io), 6 I/O88 (io), 7 I/O89 (io), 8 I/O90 (io), 9 I/O91 (io), 10 I/O92 (io), 11 I/O93 (io), 12 I/O94 (io), 13 I/O95 (io), 14 IN11 (in), 15 Y0 (in), 16 VCC (power), 17 GND (power), 18 ~{ispEN} (in), 19 ~{RESET} (in), 20 SDI/IN0 (in), 21 I/O0 (io), 22 I/O1 (io), 23 I/O2 (io), 24 I/O3 (io), 25 I/O4 (io), 26 I/O5 (io), 27 I/O6 (io), 28 I/O7 (io), 29 I/O8 (io), 30 I/O9 (io), 31 I/O10 (io), 32 I/O11 (io), 33 GND (power), 34 I/O12 (io), 35 I/O13 (io), 36 I/O14 (io), 37 I/O15 (io), 38 I/O16 (io), 39 I/O17 (io), 40 I/O18 (io), 41 I/O19 (io), 42 I/O20 (io), 43 I/O21 (io), 44 I/O22 (io), 45 I/O23 (io), 46 MODE/IN1 (in), 47 IN2 (in), 48 VCC (power), 49 GND (power), 50 SDO/IN3 (io), 51 IN4 (in), 52 I/O24 (io), 53 I/O25 (io), 54 I/O26 (io), 55 I/O27 (io), 56 I/O28 (io), 57 I/O29 (io), 58 I/O30 (io), 59 I/O31 (io), 60 I/O32 (io), 61 I/O33 (io), 62 I/O34 (io), 63 I/O35 (io), 64 GOE0 (in), 65 GND (power), 66 I/O36 (io), 67 I/O37 (io), 68 I/O38 (io), 69 I/O39 (io), 70 I/O40 (io), 71 I/O41 (io), 72 I/O42 (io), 73 I/O43 (io), 74 I/O44 (io), 75 I/O45 (io), 76 I/O46 (io), 77 I/O47 (io), 78 SCLK/IN5 (in), 79 Y3 (in), 80 Y2 (in), 81 GND (power), 82 VCC (power), 83 Y1 (in), 84 IN6 (in), 85 I/O48 (io), 86 I/O49 (io), 87 I/O50 (io), 88 I/O51 (io), 89 I/O52 (io), 90 I/O53 (io), 91 I/O54 (io), 92 I/O55 (io), 93 I/O56 (io), 94 I/O57 (io), 95 I/O58 (io), 96 I/O59 (io), 97 GND (power), 98 I/O60 (io), 99 I/O61 (io), 100 I/O62 (io), 101 I/O63 (io), 102 I/O64 (io), 103 I/O65 (io), 104 I/O66 (io), 105 I/O67 (io), 106 I/O68 (io), 107 I/O69 (io), 108 I/O70 (io), 109 I/O71 (io), 110 IN7 (in), 111 IN8 (in), 112 GND (power), 113 VCC (power), 114 GOE1 (in), 115 IN9 (in), 116 IN10 (in), 117 I/O72 (io), 118 I/O73 (io), 119 I/O74 (io), 120 I/O75 (io), 121 I/O76 (io), 122 I/O77 (io), 123 I/O78 (io), 124 I/O79 (io), 125 I/O80 (io), 126 I/O81 (io), 127 I/O82 (io), 128 I/O83 (io)

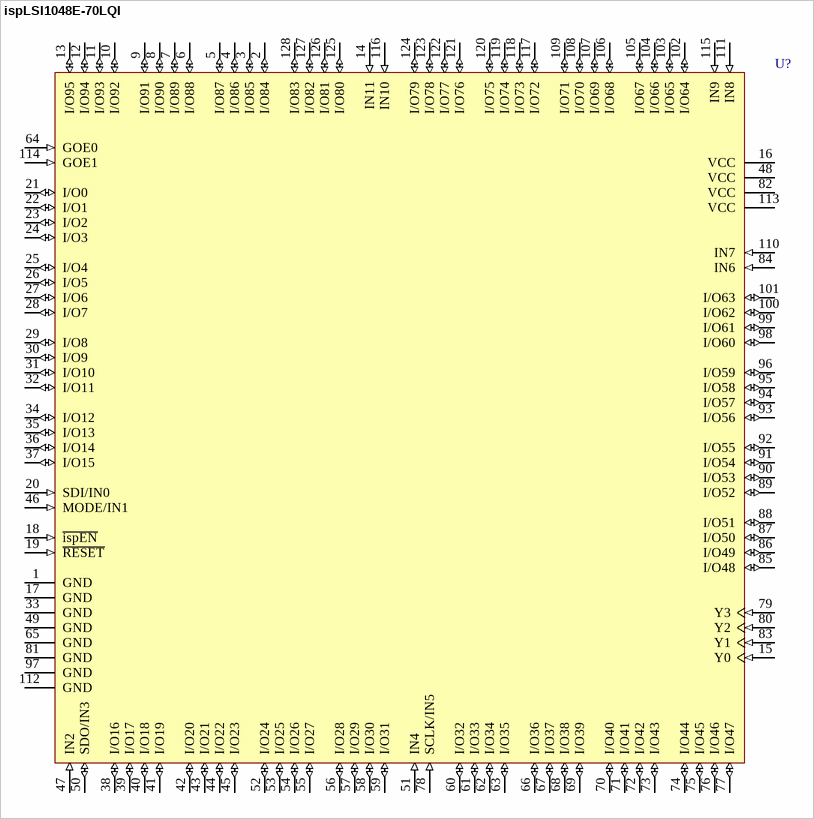
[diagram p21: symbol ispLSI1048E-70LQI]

## ispLSI1048E-70LQI
designator U?
In-System Programmable High-Density PLD; Note: Pins 20, 46, 50 and 78 have dual function capability.
footprint PQFP128_N (QFP, 128-Leads, Body 28x28mm, Pitch 0.8mm, IPC Medium Density)
footprint PQFP128_L (QFP, 128-Leads, Body 28x28mm, Pitch 0.8mm, IPC High Density)
footprint PQFP128_M (QFP, 128-Leads, Body 28x28mm, Pitch 0.8mm, IPC Low Density)
3D model 1048E-PQFP128 (128-Pin Quad Flat Pack 0.8 mm Pitch)
pins: 1 GND (power), 2 I/O84 (io), 3 I/O85 (io), 4 I/O86 (io), 5 I/O87 (io), 6 I/O88 (io), 7 I/O89 (io), 8 I/O90 (io), 9 I/O91 (io), 10 I/O92 (io), 11 I/O93 (io), 12 I/O94 (io), 13 I/O95 (io), 14 IN11 (in), 15 Y0 (in), 16 VCC (power), 17 GND (power), 18 ~{ispEN} (in), 19 ~{RESET} (in), 20 SDI/IN0 (in), 21 I/O0 (io), 22 I/O1 (io), 23 I/O2 (io), 24 I/O3 (io), 25 I/O4 (io), 26 I/O5 (io), 27 I/O6 (io), 28 I/O7 (io), 29 I/O8 (io), 30 I/O9 (io), 31 I/O10 (io), 32 I/O11 (io), 33 GND (power), 34 I/O12 (io), 35 I/O13 (io), 36 I/O14 (io), 37 I/O15 (io), 38 I/O16 (io), 39 I/O17 (io), 40 I/O18 (io), 41 I/O19 (io), 42 I/O20 (io), 43 I/O21 (io), 44 I/O22 (io), 45 I/O23 (io), 46 MODE/IN1 (in), 47 IN2 (in), 48 VCC (power), 49 GND (power), 50 SDO/IN3 (io), 51 IN4 (in), 52 I/O24 (io), 53 I/O25 (io), 54 I/O26 (io), 55 I/O27 (io), 56 I/O28 (io), 57 I/O29 (io), 58 I/O30 (io), 59 I/O31 (io), 60 I/O32 (io), 61 I/O33 (io), 62 I/O34 (io), 63 I/O35 (io), 64 GOE0 (in), 65 GND (power), 66 I/O36 (io), 67 I/O37 (io), 68 I/O38 (io), 69 I/O39 (io), 70 I/O40 (io), 71 I/O41 (io), 72 I/O42 (io), 73 I/O43 (io), 74 I/O44 (io), 75 I/O45 (io), 76 I/O46 (io), 77 I/O47 (io), 78 SCLK/IN5 (in), 79 Y3 (in), 80 Y2 (in), 81 GND (power), 82 VCC (power), 83 Y1 (in), 84 IN6 (in), 85 I/O48 (io), 86 I/O49 (io), 87 I/O50 (io), 88 I/O51 (io), 89 I/O52 (io), 90 I/O53 (io), 91 I/O54 (io), 92 I/O55 (io), 93 I/O56 (io), 94 I/O57 (io), 95 I/O58 (io), 96 I/O59 (io), 97 GND (power), 98 I/O60 (io), 99 I/O61 (io), 100 I/O62 (io), 101 I/O63 (io), 102 I/O64 (io), 103 I/O65 (io), 104 I/O66 (io), 105 I/O67 (io), 106 I/O68 (io), 107 I/O69 (io), 108 I/O70 (io), 109 I/O71 (io), 110 IN7 (in), 111 IN8 (in), 112 GND (power), 113 VCC (power), 114 GOE1 (in), 115 IN9 (in), 116 IN10 (in), 117 I/O72 (io), 118 I/O73 (io), 119 I/O74 (io), 120 I/O75 (io), 121 I/O76 (io), 122 I/O77 (io), 123 I/O78 (io), 124 I/O79 (io), 125 I/O80 (io), 126 I/O81 (io), 127 I/O82 (io), 128 I/O83 (io)

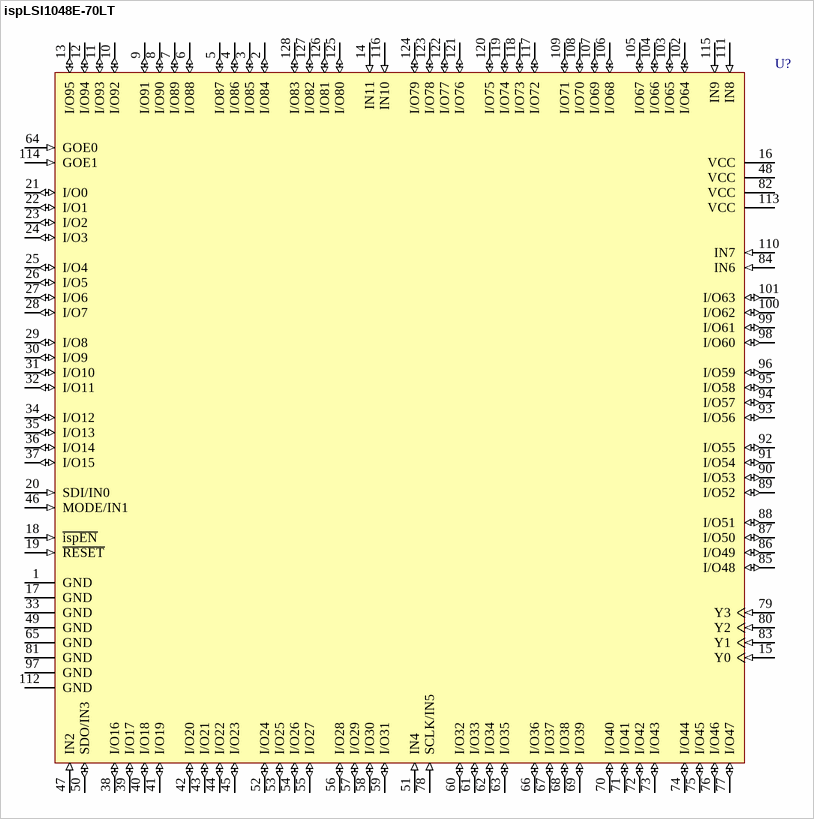
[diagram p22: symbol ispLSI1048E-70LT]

## ispLSI1048E-70LT
designator U?
In-System Programmable High-Density PLD; Note: Pins 20, 46, 50 and 78 have dual function capability.
footprint TQFP128_N (Thin QFP, 128-Leads, Body 14x14mm, Pitch 0.4mm, IPC Medium Density)
footprint TQFP128_L (Thin QFP, 128-Leads, Body 14x14mm, Pitch 0.4mm, IPC High Density)
footprint TQFP128_M (Thin QFP, 128-Leads, Body 14x14mm, Pitch 0.4mm, IPC Low Density)
3D model 1048E-TQFP128 (128-Pin Thin Quad Flat Pack 0.4 mm Pitch)
pins: 1 GND (power), 2 I/O84 (io), 3 I/O85 (io), 4 I/O86 (io), 5 I/O87 (io), 6 I/O88 (io), 7 I/O89 (io), 8 I/O90 (io), 9 I/O91 (io), 10 I/O92 (io), 11 I/O93 (io), 12 I/O94 (io), 13 I/O95 (io), 14 IN11 (in), 15 Y0 (in), 16 VCC (power), 17 GND (power), 18 ~{ispEN} (in), 19 ~{RESET} (in), 20 SDI/IN0 (in), 21 I/O0 (io), 22 I/O1 (io), 23 I/O2 (io), 24 I/O3 (io), 25 I/O4 (io), 26 I/O5 (io), 27 I/O6 (io), 28 I/O7 (io), 29 I/O8 (io), 30 I/O9 (io), 31 I/O10 (io), 32 I/O11 (io), 33 GND (power), 34 I/O12 (io), 35 I/O13 (io), 36 I/O14 (io), 37 I/O15 (io), 38 I/O16 (io), 39 I/O17 (io), 40 I/O18 (io), 41 I/O19 (io), 42 I/O20 (io), 43 I/O21 (io), 44 I/O22 (io), 45 I/O23 (io), 46 MODE/IN1 (in), 47 IN2 (in), 48 VCC (power), 49 GND (power), 50 SDO/IN3 (io), 51 IN4 (in), 52 I/O24 (io), 53 I/O25 (io), 54 I/O26 (io), 55 I/O27 (io), 56 I/O28 (io), 57 I/O29 (io), 58 I/O30 (io), 59 I/O31 (io), 60 I/O32 (io), 61 I/O33 (io), 62 I/O34 (io), 63 I/O35 (io), 64 GOE0 (in), 65 GND (power), 66 I/O36 (io), 67 I/O37 (io), 68 I/O38 (io), 69 I/O39 (io), 70 I/O40 (io), 71 I/O41 (io), 72 I/O42 (io), 73 I/O43 (io), 74 I/O44 (io), 75 I/O45 (io), 76 I/O46 (io), 77 I/O47 (io), 78 SCLK/IN5 (in), 79 Y3 (in), 80 Y2 (in), 81 GND (power), 82 VCC (power), 83 Y1 (in), 84 IN6 (in), 85 I/O48 (io), 86 I/O49 (io), 87 I/O50 (io), 88 I/O51 (io), 89 I/O52 (io), 90 I/O53 (io), 91 I/O54 (io), 92 I/O55 (io), 93 I/O56 (io), 94 I/O57 (io), 95 I/O58 (io), 96 I/O59 (io), 97 GND (power), 98 I/O60 (io), 99 I/O61 (io), 100 I/O62 (io), 101 I/O63 (io), 102 I/O64 (io), 103 I/O65 (io), 104 I/O66 (io), 105 I/O67 (io), 106 I/O68 (io), 107 I/O69 (io), 108 I/O70 (io), 109 I/O71 (io), 110 IN7 (in), 111 IN8 (in), 112 GND (power), 113 VCC (power), 114 GOE1 (in), 115 IN9 (in), 116 IN10 (in), 117 I/O72 (io), 118 I/O73 (io), 119 I/O74 (io), 120 I/O75 (io), 121 I/O76 (io), 122 I/O77 (io), 123 I/O78 (io), 124 I/O79 (io), 125 I/O80 (io), 126 I/O81 (io), 127 I/O82 (io), 128 I/O83 (io)

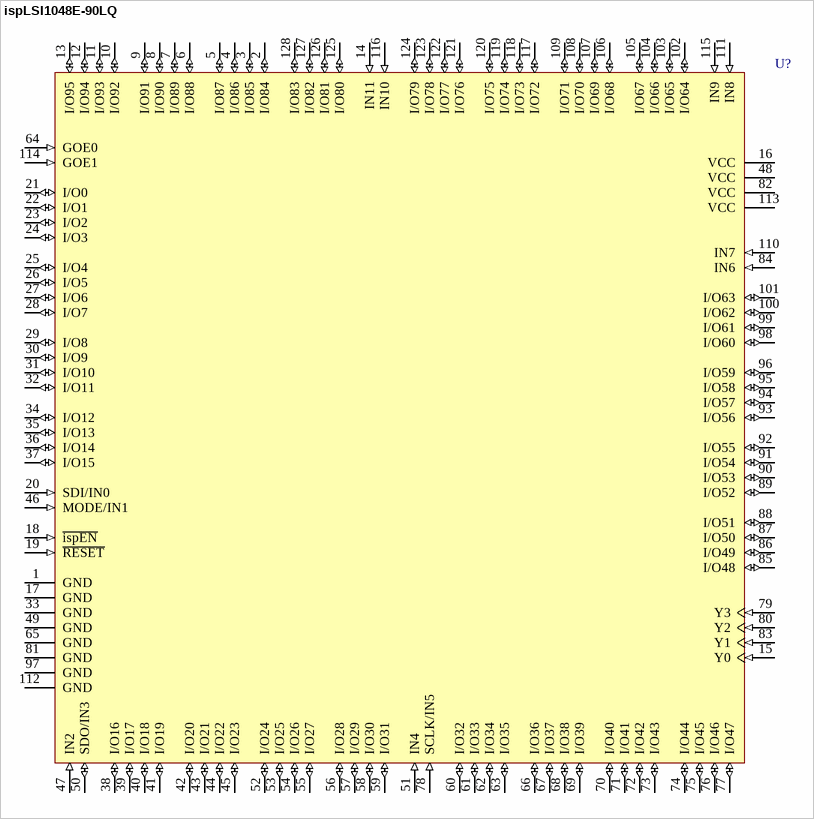
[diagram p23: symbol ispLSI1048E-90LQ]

## ispLSI1048E-90LQ
designator U?
In-System Programmable High-Density PLD; Note: Pins 20, 46, 50 and 78 have dual function capability.
footprint PQFP128_N (QFP, 128-Leads, Body 28x28mm, Pitch 0.8mm, IPC Medium Density)
footprint PQFP128_L (QFP, 128-Leads, Body 28x28mm, Pitch 0.8mm, IPC High Density)
footprint PQFP128_M (QFP, 128-Leads, Body 28x28mm, Pitch 0.8mm, IPC Low Density)
3D model 1048E-PQFP128 (128-Pin Quad Flat Pack 0.8 mm Pitch)
pins: 1 GND (power), 2 I/O84 (io), 3 I/O85 (io), 4 I/O86 (io), 5 I/O87 (io), 6 I/O88 (io), 7 I/O89 (io), 8 I/O90 (io), 9 I/O91 (io), 10 I/O92 (io), 11 I/O93 (io), 12 I/O94 (io), 13 I/O95 (io), 14 IN11 (in), 15 Y0 (in), 16 VCC (power), 17 GND (power), 18 ~{ispEN} (in), 19 ~{RESET} (in), 20 SDI/IN0 (in), 21 I/O0 (io), 22 I/O1 (io), 23 I/O2 (io), 24 I/O3 (io), 25 I/O4 (io), 26 I/O5 (io), 27 I/O6 (io), 28 I/O7 (io), 29 I/O8 (io), 30 I/O9 (io), 31 I/O10 (io), 32 I/O11 (io), 33 GND (power), 34 I/O12 (io), 35 I/O13 (io), 36 I/O14 (io), 37 I/O15 (io), 38 I/O16 (io), 39 I/O17 (io), 40 I/O18 (io), 41 I/O19 (io), 42 I/O20 (io), 43 I/O21 (io), 44 I/O22 (io), 45 I/O23 (io), 46 MODE/IN1 (in), 47 IN2 (in), 48 VCC (power), 49 GND (power), 50 SDO/IN3 (io), 51 IN4 (in), 52 I/O24 (io), 53 I/O25 (io), 54 I/O26 (io), 55 I/O27 (io), 56 I/O28 (io), 57 I/O29 (io), 58 I/O30 (io), 59 I/O31 (io), 60 I/O32 (io), 61 I/O33 (io), 62 I/O34 (io), 63 I/O35 (io), 64 GOE0 (in), 65 GND (power), 66 I/O36 (io), 67 I/O37 (io), 68 I/O38 (io), 69 I/O39 (io), 70 I/O40 (io), 71 I/O41 (io), 72 I/O42 (io), 73 I/O43 (io), 74 I/O44 (io), 75 I/O45 (io), 76 I/O46 (io), 77 I/O47 (io), 78 SCLK/IN5 (in), 79 Y3 (in), 80 Y2 (in), 81 GND (power), 82 VCC (power), 83 Y1 (in), 84 IN6 (in), 85 I/O48 (io), 86 I/O49 (io), 87 I/O50 (io), 88 I/O51 (io), 89 I/O52 (io), 90 I/O53 (io), 91 I/O54 (io), 92 I/O55 (io), 93 I/O56 (io), 94 I/O57 (io), 95 I/O58 (io), 96 I/O59 (io), 97 GND (power), 98 I/O60 (io), 99 I/O61 (io), 100 I/O62 (io), 101 I/O63 (io), 102 I/O64 (io), 103 I/O65 (io), 104 I/O66 (io), 105 I/O67 (io), 106 I/O68 (io), 107 I/O69 (io), 108 I/O70 (io), 109 I/O71 (io), 110 IN7 (in), 111 IN8 (in), 112 GND (power), 113 VCC (power), 114 GOE1 (in), 115 IN9 (in), 116 IN10 (in), 117 I/O72 (io), 118 I/O73 (io), 119 I/O74 (io), 120 I/O75 (io), 121 I/O76 (io), 122 I/O77 (io), 123 I/O78 (io), 124 I/O79 (io), 125 I/O80 (io), 126 I/O81 (io), 127 I/O82 (io), 128 I/O83 (io)

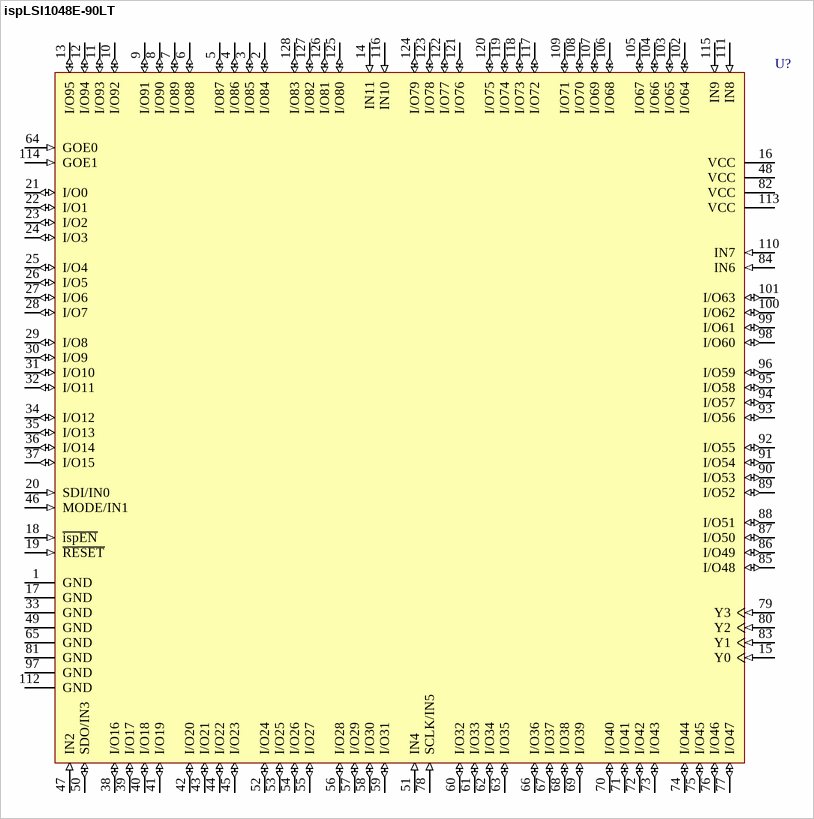
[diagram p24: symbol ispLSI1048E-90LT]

## ispLSI1048E-90LT
designator U?
In-System Programmable High-Density PLD; Note: Pins 20, 46, 50 and 78 have dual function capability.
footprint TQFP128_N (Thin QFP, 128-Leads, Body 14x14mm, Pitch 0.4mm, IPC Medium Density)
footprint TQFP128_L (Thin QFP, 128-Leads, Body 14x14mm, Pitch 0.4mm, IPC High Density)
footprint TQFP128_M (Thin QFP, 128-Leads, Body 14x14mm, Pitch 0.4mm, IPC Low Density)
3D model 1048E-TQFP128 (128-Pin Thin Quad Flat Pack 0.4 mm Pitch)
pins: 1 GND (power), 2 I/O84 (io), 3 I/O85 (io), 4 I/O86 (io), 5 I/O87 (io), 6 I/O88 (io), 7 I/O89 (io), 8 I/O90 (io), 9 I/O91 (io), 10 I/O92 (io), 11 I/O93 (io), 12 I/O94 (io), 13 I/O95 (io), 14 IN11 (in), 15 Y0 (in), 16 VCC (power), 17 GND (power), 18 ~{ispEN} (in), 19 ~{RESET} (in), 20 SDI/IN0 (in), 21 I/O0 (io), 22 I/O1 (io), 23 I/O2 (io), 24 I/O3 (io), 25 I/O4 (io), 26 I/O5 (io), 27 I/O6 (io), 28 I/O7 (io), 29 I/O8 (io), 30 I/O9 (io), 31 I/O10 (io), 32 I/O11 (io), 33 GND (power), 34 I/O12 (io), 35 I/O13 (io), 36 I/O14 (io), 37 I/O15 (io), 38 I/O16 (io), 39 I/O17 (io), 40 I/O18 (io), 41 I/O19 (io), 42 I/O20 (io), 43 I/O21 (io), 44 I/O22 (io), 45 I/O23 (io), 46 MODE/IN1 (in), 47 IN2 (in), 48 VCC (power), 49 GND (power), 50 SDO/IN3 (io), 51 IN4 (in), 52 I/O24 (io), 53 I/O25 (io), 54 I/O26 (io), 55 I/O27 (io), 56 I/O28 (io), 57 I/O29 (io), 58 I/O30 (io), 59 I/O31 (io), 60 I/O32 (io), 61 I/O33 (io), 62 I/O34 (io), 63 I/O35 (io), 64 GOE0 (in), 65 GND (power), 66 I/O36 (io), 67 I/O37 (io), 68 I/O38 (io), 69 I/O39 (io), 70 I/O40 (io), 71 I/O41 (io), 72 I/O42 (io), 73 I/O43 (io), 74 I/O44 (io), 75 I/O45 (io), 76 I/O46 (io), 77 I/O47 (io), 78 SCLK/IN5 (in), 79 Y3 (in), 80 Y2 (in), 81 GND (power), 82 VCC (power), 83 Y1 (in), 84 IN6 (in), 85 I/O48 (io), 86 I/O49 (io), 87 I/O50 (io), 88 I/O51 (io), 89 I/O52 (io), 90 I/O53 (io), 91 I/O54 (io), 92 I/O55 (io), 93 I/O56 (io), 94 I/O57 (io), 95 I/O58 (io), 96 I/O59 (io), 97 GND (power), 98 I/O60 (io), 99 I/O61 (io), 100 I/O62 (io), 101 I/O63 (io), 102 I/O64 (io), 103 I/O65 (io), 104 I/O66 (io), 105 I/O67 (io), 106 I/O68 (io), 107 I/O69 (io), 108 I/O70 (io), 109 I/O71 (io), 110 IN7 (in), 111 IN8 (in), 112 GND (power), 113 VCC (power), 114 GOE1 (in), 115 IN9 (in), 116 IN10 (in), 117 I/O72 (io), 118 I/O73 (io), 119 I/O74 (io), 120 I/O75 (io), 121 I/O76 (io), 122 I/O77 (io), 123 I/O78 (io), 124 I/O79 (io), 125 I/O80 (io), 126 I/O81 (io), 127 I/O82 (io), 128 I/O83 (io)

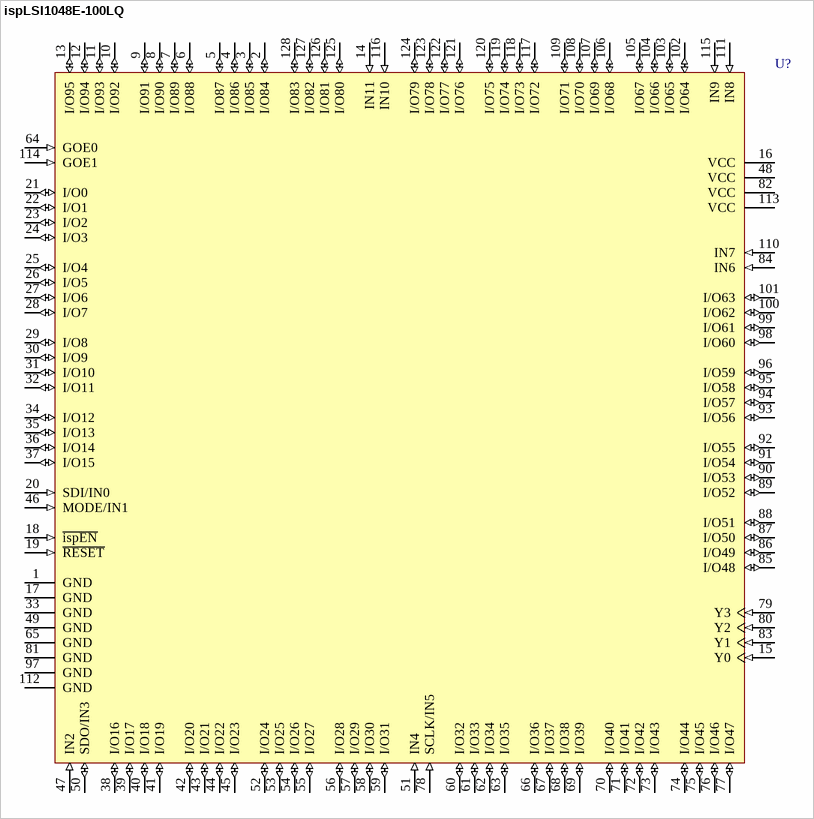
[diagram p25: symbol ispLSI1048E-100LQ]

## ispLSI1048E-100LQ
designator U?
In-System Programmable High-Density PLD; Note: Pins 20, 46, 50 and 78 have dual function capability.
footprint PQFP128_N (QFP, 128-Leads, Body 28x28mm, Pitch 0.8mm, IPC Medium Density)
footprint PQFP128_L (QFP, 128-Leads, Body 28x28mm, Pitch 0.8mm, IPC High Density)
footprint PQFP128_M (QFP, 128-Leads, Body 28x28mm, Pitch 0.8mm, IPC Low Density)
3D model 1048E-PQFP128 (128-Pin Quad Flat Pack 0.8 mm Pitch)
pins: 1 GND (power), 2 I/O84 (io), 3 I/O85 (io), 4 I/O86 (io), 5 I/O87 (io), 6 I/O88 (io), 7 I/O89 (io), 8 I/O90 (io), 9 I/O91 (io), 10 I/O92 (io), 11 I/O93 (io), 12 I/O94 (io), 13 I/O95 (io), 14 IN11 (in), 15 Y0 (in), 16 VCC (power), 17 GND (power), 18 ~{ispEN} (in), 19 ~{RESET} (in), 20 SDI/IN0 (in), 21 I/O0 (io), 22 I/O1 (io), 23 I/O2 (io), 24 I/O3 (io), 25 I/O4 (io), 26 I/O5 (io), 27 I/O6 (io), 28 I/O7 (io), 29 I/O8 (io), 30 I/O9 (io), 31 I/O10 (io), 32 I/O11 (io), 33 GND (power), 34 I/O12 (io), 35 I/O13 (io), 36 I/O14 (io), 37 I/O15 (io), 38 I/O16 (io), 39 I/O17 (io), 40 I/O18 (io), 41 I/O19 (io), 42 I/O20 (io), 43 I/O21 (io), 44 I/O22 (io), 45 I/O23 (io), 46 MODE/IN1 (in), 47 IN2 (in), 48 VCC (power), 49 GND (power), 50 SDO/IN3 (io), 51 IN4 (in), 52 I/O24 (io), 53 I/O25 (io), 54 I/O26 (io), 55 I/O27 (io), 56 I/O28 (io), 57 I/O29 (io), 58 I/O30 (io), 59 I/O31 (io), 60 I/O32 (io), 61 I/O33 (io), 62 I/O34 (io), 63 I/O35 (io), 64 GOE0 (in), 65 GND (power), 66 I/O36 (io), 67 I/O37 (io), 68 I/O38 (io), 69 I/O39 (io), 70 I/O40 (io), 71 I/O41 (io), 72 I/O42 (io), 73 I/O43 (io), 74 I/O44 (io), 75 I/O45 (io), 76 I/O46 (io), 77 I/O47 (io), 78 SCLK/IN5 (in), 79 Y3 (in), 80 Y2 (in), 81 GND (power), 82 VCC (power), 83 Y1 (in), 84 IN6 (in), 85 I/O48 (io), 86 I/O49 (io), 87 I/O50 (io), 88 I/O51 (io), 89 I/O52 (io), 90 I/O53 (io), 91 I/O54 (io), 92 I/O55 (io), 93 I/O56 (io), 94 I/O57 (io), 95 I/O58 (io), 96 I/O59 (io), 97 GND (power), 98 I/O60 (io), 99 I/O61 (io), 100 I/O62 (io), 101 I/O63 (io), 102 I/O64 (io), 103 I/O65 (io), 104 I/O66 (io), 105 I/O67 (io), 106 I/O68 (io), 107 I/O69 (io), 108 I/O70 (io), 109 I/O71 (io), 110 IN7 (in), 111 IN8 (in), 112 GND (power), 113 VCC (power), 114 GOE1 (in), 115 IN9 (in), 116 IN10 (in), 117 I/O72 (io), 118 I/O73 (io), 119 I/O74 (io), 120 I/O75 (io), 121 I/O76 (io), 122 I/O77 (io), 123 I/O78 (io), 124 I/O79 (io), 125 I/O80 (io), 126 I/O81 (io), 127 I/O82 (io), 128 I/O83 (io)

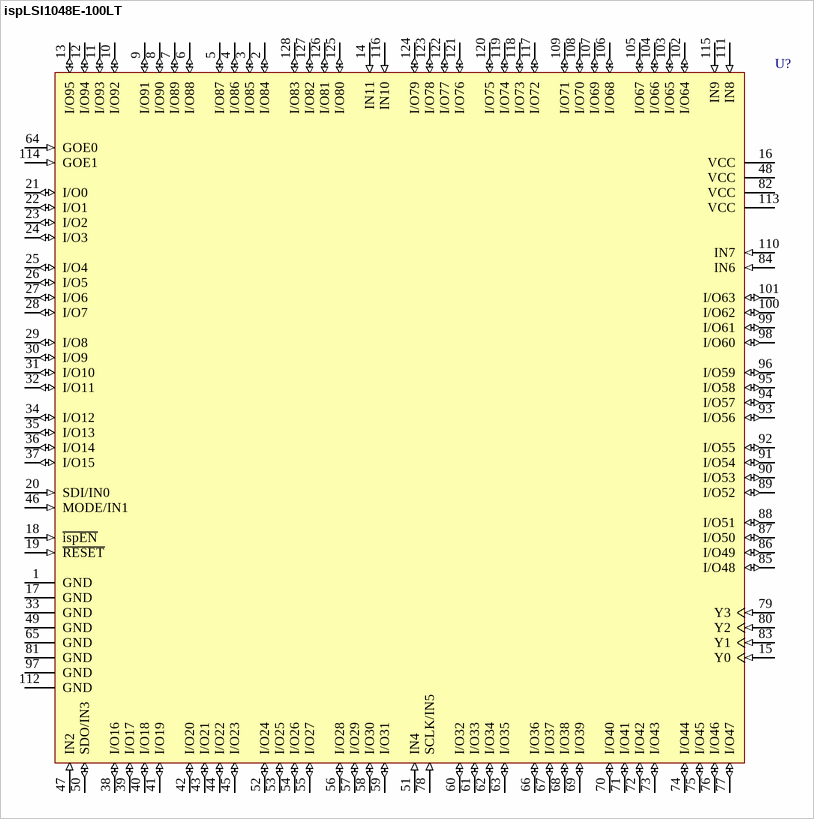
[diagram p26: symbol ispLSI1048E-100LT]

## ispLSI1048E-100LT
designator U?
In-System Programmable High-Density PLD; Note: Pins 20, 46, 50 and 78 have dual function capability.
footprint TQFP128_N (Thin QFP, 128-Leads, Body 14x14mm, Pitch 0.4mm, IPC Medium Density)
footprint TQFP128_L (Thin QFP, 128-Leads, Body 14x14mm, Pitch 0.4mm, IPC High Density)
footprint TQFP128_M (Thin QFP, 128-Leads, Body 14x14mm, Pitch 0.4mm, IPC Low Density)
3D model 1048E-TQFP128 (128-Pin Thin Quad Flat Pack 0.4 mm Pitch)
pins: 1 GND (power), 2 I/O84 (io), 3 I/O85 (io), 4 I/O86 (io), 5 I/O87 (io), 6 I/O88 (io), 7 I/O89 (io), 8 I/O90 (io), 9 I/O91 (io), 10 I/O92 (io), 11 I/O93 (io), 12 I/O94 (io), 13 I/O95 (io), 14 IN11 (in), 15 Y0 (in), 16 VCC (power), 17 GND (power), 18 ~{ispEN} (in), 19 ~{RESET} (in), 20 SDI/IN0 (in), 21 I/O0 (io), 22 I/O1 (io), 23 I/O2 (io), 24 I/O3 (io), 25 I/O4 (io), 26 I/O5 (io), 27 I/O6 (io), 28 I/O7 (io), 29 I/O8 (io), 30 I/O9 (io), 31 I/O10 (io), 32 I/O11 (io), 33 GND (power), 34 I/O12 (io), 35 I/O13 (io), 36 I/O14 (io), 37 I/O15 (io), 38 I/O16 (io), 39 I/O17 (io), 40 I/O18 (io), 41 I/O19 (io), 42 I/O20 (io), 43 I/O21 (io), 44 I/O22 (io), 45 I/O23 (io), 46 MODE/IN1 (in), 47 IN2 (in), 48 VCC (power), 49 GND (power), 50 SDO/IN3 (io), 51 IN4 (in), 52 I/O24 (io), 53 I/O25 (io), 54 I/O26 (io), 55 I/O27 (io), 56 I/O28 (io), 57 I/O29 (io), 58 I/O30 (io), 59 I/O31 (io), 60 I/O32 (io), 61 I/O33 (io), 62 I/O34 (io), 63 I/O35 (io), 64 GOE0 (in), 65 GND (power), 66 I/O36 (io), 67 I/O37 (io), 68 I/O38 (io), 69 I/O39 (io), 70 I/O40 (io), 71 I/O41 (io), 72 I/O42 (io), 73 I/O43 (io), 74 I/O44 (io), 75 I/O45 (io), 76 I/O46 (io), 77 I/O47 (io), 78 SCLK/IN5 (in), 79 Y3 (in), 80 Y2 (in), 81 GND (power), 82 VCC (power), 83 Y1 (in), 84 IN6 (in), 85 I/O48 (io), 86 I/O49 (io), 87 I/O50 (io), 88 I/O51 (io), 89 I/O52 (io), 90 I/O53 (io), 91 I/O54 (io), 92 I/O55 (io), 93 I/O56 (io), 94 I/O57 (io), 95 I/O58 (io), 96 I/O59 (io), 97 GND (power), 98 I/O60 (io), 99 I/O61 (io), 100 I/O62 (io), 101 I/O63 (io), 102 I/O64 (io), 103 I/O65 (io), 104 I/O66 (io), 105 I/O67 (io), 106 I/O68 (io), 107 I/O69 (io), 108 I/O70 (io), 109 I/O71 (io), 110 IN7 (in), 111 IN8 (in), 112 GND (power), 113 VCC (power), 114 GOE1 (in), 115 IN9 (in), 116 IN10 (in), 117 I/O72 (io), 118 I/O73 (io), 119 I/O74 (io), 120 I/O75 (io), 121 I/O76 (io), 122 I/O77 (io), 123 I/O78 (io), 124 I/O79 (io), 125 I/O80 (io), 126 I/O81 (io), 127 I/O82 (io), 128 I/O83 (io)

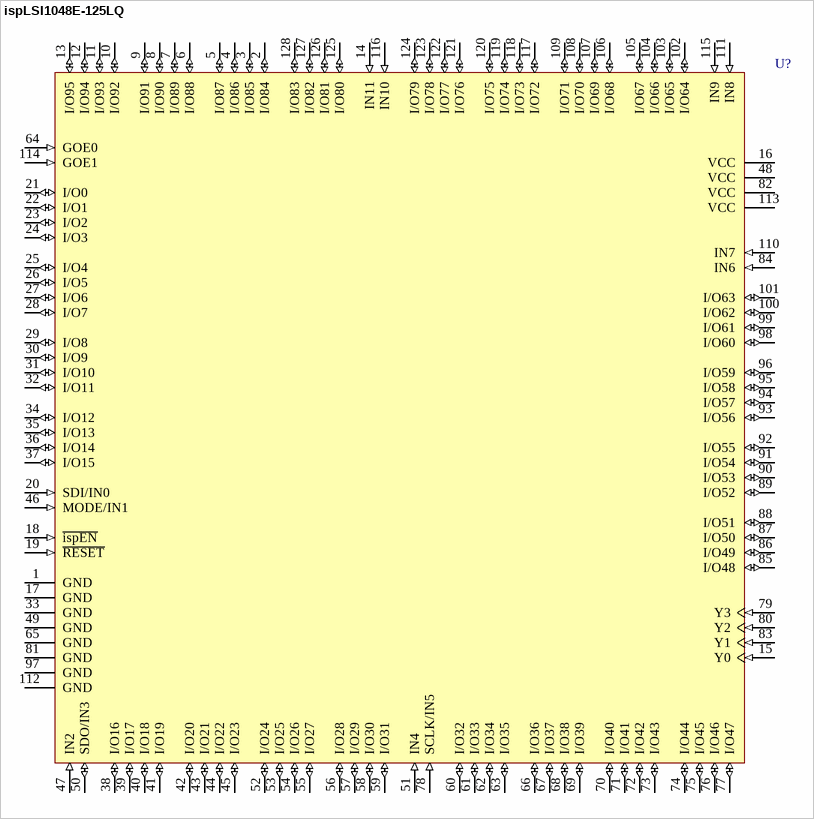
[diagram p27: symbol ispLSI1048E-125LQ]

## ispLSI1048E-125LQ
designator U?
In-System Programmable High-Density PLD; Note: Pins 20, 46, 50 and 78 have dual function capability.
footprint PQFP128_N (QFP, 128-Leads, Body 28x28mm, Pitch 0.8mm, IPC Medium Density)
footprint PQFP128_L (QFP, 128-Leads, Body 28x28mm, Pitch 0.8mm, IPC High Density)
footprint PQFP128_M (QFP, 128-Leads, Body 28x28mm, Pitch 0.8mm, IPC Low Density)
3D model 1048E-PQFP128 (128-Pin Quad Flat Pack 0.8 mm Pitch)
pins: 1 GND (power), 2 I/O84 (io), 3 I/O85 (io), 4 I/O86 (io), 5 I/O87 (io), 6 I/O88 (io), 7 I/O89 (io), 8 I/O90 (io), 9 I/O91 (io), 10 I/O92 (io), 11 I/O93 (io), 12 I/O94 (io), 13 I/O95 (io), 14 IN11 (in), 15 Y0 (in), 16 VCC (power), 17 GND (power), 18 ~{ispEN} (in), 19 ~{RESET} (in), 20 SDI/IN0 (in), 21 I/O0 (io), 22 I/O1 (io), 23 I/O2 (io), 24 I/O3 (io), 25 I/O4 (io), 26 I/O5 (io), 27 I/O6 (io), 28 I/O7 (io), 29 I/O8 (io), 30 I/O9 (io), 31 I/O10 (io), 32 I/O11 (io), 33 GND (power), 34 I/O12 (io), 35 I/O13 (io), 36 I/O14 (io), 37 I/O15 (io), 38 I/O16 (io), 39 I/O17 (io), 40 I/O18 (io), 41 I/O19 (io), 42 I/O20 (io), 43 I/O21 (io), 44 I/O22 (io), 45 I/O23 (io), 46 MODE/IN1 (in), 47 IN2 (in), 48 VCC (power), 49 GND (power), 50 SDO/IN3 (io), 51 IN4 (in), 52 I/O24 (io), 53 I/O25 (io), 54 I/O26 (io), 55 I/O27 (io), 56 I/O28 (io), 57 I/O29 (io), 58 I/O30 (io), 59 I/O31 (io), 60 I/O32 (io), 61 I/O33 (io), 62 I/O34 (io), 63 I/O35 (io), 64 GOE0 (in), 65 GND (power), 66 I/O36 (io), 67 I/O37 (io), 68 I/O38 (io), 69 I/O39 (io), 70 I/O40 (io), 71 I/O41 (io), 72 I/O42 (io), 73 I/O43 (io), 74 I/O44 (io), 75 I/O45 (io), 76 I/O46 (io), 77 I/O47 (io), 78 SCLK/IN5 (in), 79 Y3 (in), 80 Y2 (in), 81 GND (power), 82 VCC (power), 83 Y1 (in), 84 IN6 (in), 85 I/O48 (io), 86 I/O49 (io), 87 I/O50 (io), 88 I/O51 (io), 89 I/O52 (io), 90 I/O53 (io), 91 I/O54 (io), 92 I/O55 (io), 93 I/O56 (io), 94 I/O57 (io), 95 I/O58 (io), 96 I/O59 (io), 97 GND (power), 98 I/O60 (io), 99 I/O61 (io), 100 I/O62 (io), 101 I/O63 (io), 102 I/O64 (io), 103 I/O65 (io), 104 I/O66 (io), 105 I/O67 (io), 106 I/O68 (io), 107 I/O69 (io), 108 I/O70 (io), 109 I/O71 (io), 110 IN7 (in), 111 IN8 (in), 112 GND (power), 113 VCC (power), 114 GOE1 (in), 115 IN9 (in), 116 IN10 (in), 117 I/O72 (io), 118 I/O73 (io), 119 I/O74 (io), 120 I/O75 (io), 121 I/O76 (io), 122 I/O77 (io), 123 I/O78 (io), 124 I/O79 (io), 125 I/O80 (io), 126 I/O81 (io), 127 I/O82 (io), 128 I/O83 (io)

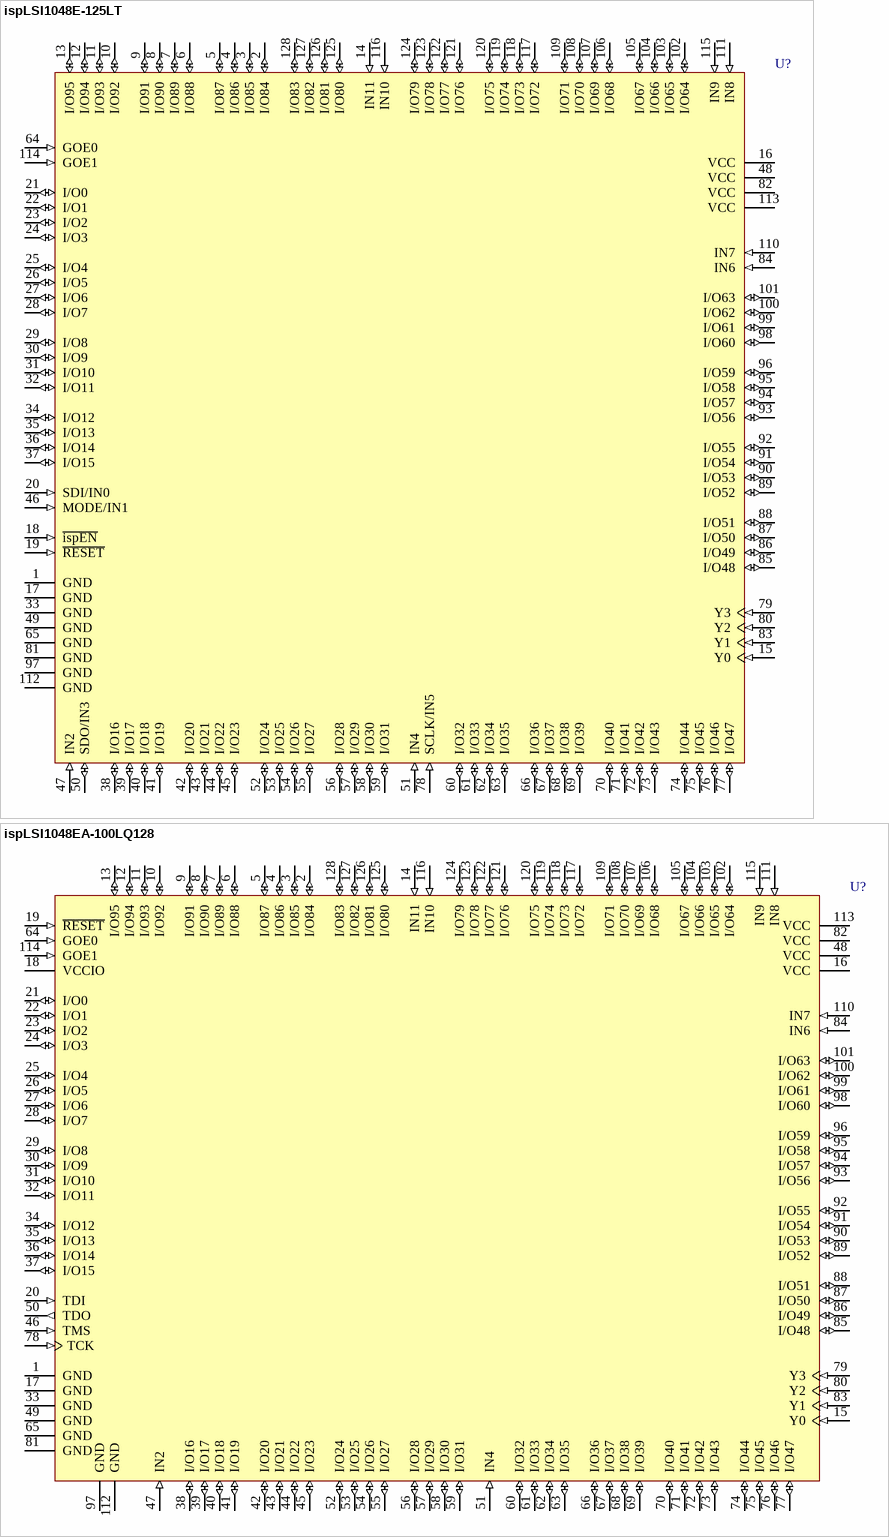
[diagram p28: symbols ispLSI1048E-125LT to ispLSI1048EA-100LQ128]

## ispLSI1048E-125LT
designator U?
In-System Programmable High-Density PLD; Note: Pins 20, 46, 50 and 78 have dual function capability.
footprint TQFP128_N (Thin QFP, 128-Leads, Body 14x14mm, Pitch 0.4mm, IPC Medium Density)
footprint TQFP128_L (Thin QFP, 128-Leads, Body 14x14mm, Pitch 0.4mm, IPC High Density)
footprint TQFP128_M (Thin QFP, 128-Leads, Body 14x14mm, Pitch 0.4mm, IPC Low Density)
3D model 1048E-TQFP128 (128-Pin Thin Quad Flat Pack 0.4 mm Pitch)
pins: 1 GND (power), 2 I/O84 (io), 3 I/O85 (io), 4 I/O86 (io), 5 I/O87 (io), 6 I/O88 (io), 7 I/O89 (io), 8 I/O90 (io), 9 I/O91 (io), 10 I/O92 (io), 11 I/O93 (io), 12 I/O94 (io), 13 I/O95 (io), 14 IN11 (in), 15 Y0 (in), 16 VCC (power), 17 GND (power), 18 ~{ispEN} (in), 19 ~{RESET} (in), 20 SDI/IN0 (in), 21 I/O0 (io), 22 I/O1 (io), 23 I/O2 (io), 24 I/O3 (io), 25 I/O4 (io), 26 I/O5 (io), 27 I/O6 (io), 28 I/O7 (io), 29 I/O8 (io), 30 I/O9 (io), 31 I/O10 (io), 32 I/O11 (io), 33 GND (power), 34 I/O12 (io), 35 I/O13 (io), 36 I/O14 (io), 37 I/O15 (io), 38 I/O16 (io), 39 I/O17 (io), 40 I/O18 (io), 41 I/O19 (io), 42 I/O20 (io), 43 I/O21 (io), 44 I/O22 (io), 45 I/O23 (io), 46 MODE/IN1 (in), 47 IN2 (in), 48 VCC (power), 49 GND (power), 50 SDO/IN3 (io), 51 IN4 (in), 52 I/O24 (io), 53 I/O25 (io), 54 I/O26 (io), 55 I/O27 (io), 56 I/O28 (io), 57 I/O29 (io), 58 I/O30 (io), 59 I/O31 (io), 60 I/O32 (io), 61 I/O33 (io), 62 I/O34 (io), 63 I/O35 (io), 64 GOE0 (in), 65 GND (power), 66 I/O36 (io), 67 I/O37 (io), 68 I/O38 (io), 69 I/O39 (io), 70 I/O40 (io), 71 I/O41 (io), 72 I/O42 (io), 73 I/O43 (io), 74 I/O44 (io), 75 I/O45 (io), 76 I/O46 (io), 77 I/O47 (io), 78 SCLK/IN5 (in), 79 Y3 (in), 80 Y2 (in), 81 GND (power), 82 VCC (power), 83 Y1 (in), 84 IN6 (in), 85 I/O48 (io), 86 I/O49 (io), 87 I/O50 (io), 88 I/O51 (io), 89 I/O52 (io), 90 I/O53 (io), 91 I/O54 (io), 92 I/O55 (io), 93 I/O56 (io), 94 I/O57 (io), 95 I/O58 (io), 96 I/O59 (io), 97 GND (power), 98 I/O60 (io), 99 I/O61 (io), 100 I/O62 (io), 101 I/O63 (io), 102 I/O64 (io), 103 I/O65 (io), 104 I/O66 (io), 105 I/O67 (io), 106 I/O68 (io), 107 I/O69 (io), 108 I/O70 (io), 109 I/O71 (io), 110 IN7 (in), 111 IN8 (in), 112 GND (power), 113 VCC (power), 114 GOE1 (in), 115 IN9 (in), 116 IN10 (in), 117 I/O72 (io), 118 I/O73 (io), 119 I/O74 (io), 120 I/O75 (io), 121 I/O76 (io), 122 I/O77 (io), 123 I/O78 (io), 124 I/O79 (io), 125 I/O80 (io), 126 I/O81 (io), 127 I/O82 (io), 128 I/O83 (io)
